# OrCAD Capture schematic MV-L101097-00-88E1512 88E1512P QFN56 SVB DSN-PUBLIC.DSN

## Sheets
1 Title Page: title: 88E1512 / 88E1512P 56-QFN Evaluation Board (Schematics); rev: -; note: MV-L101097-00
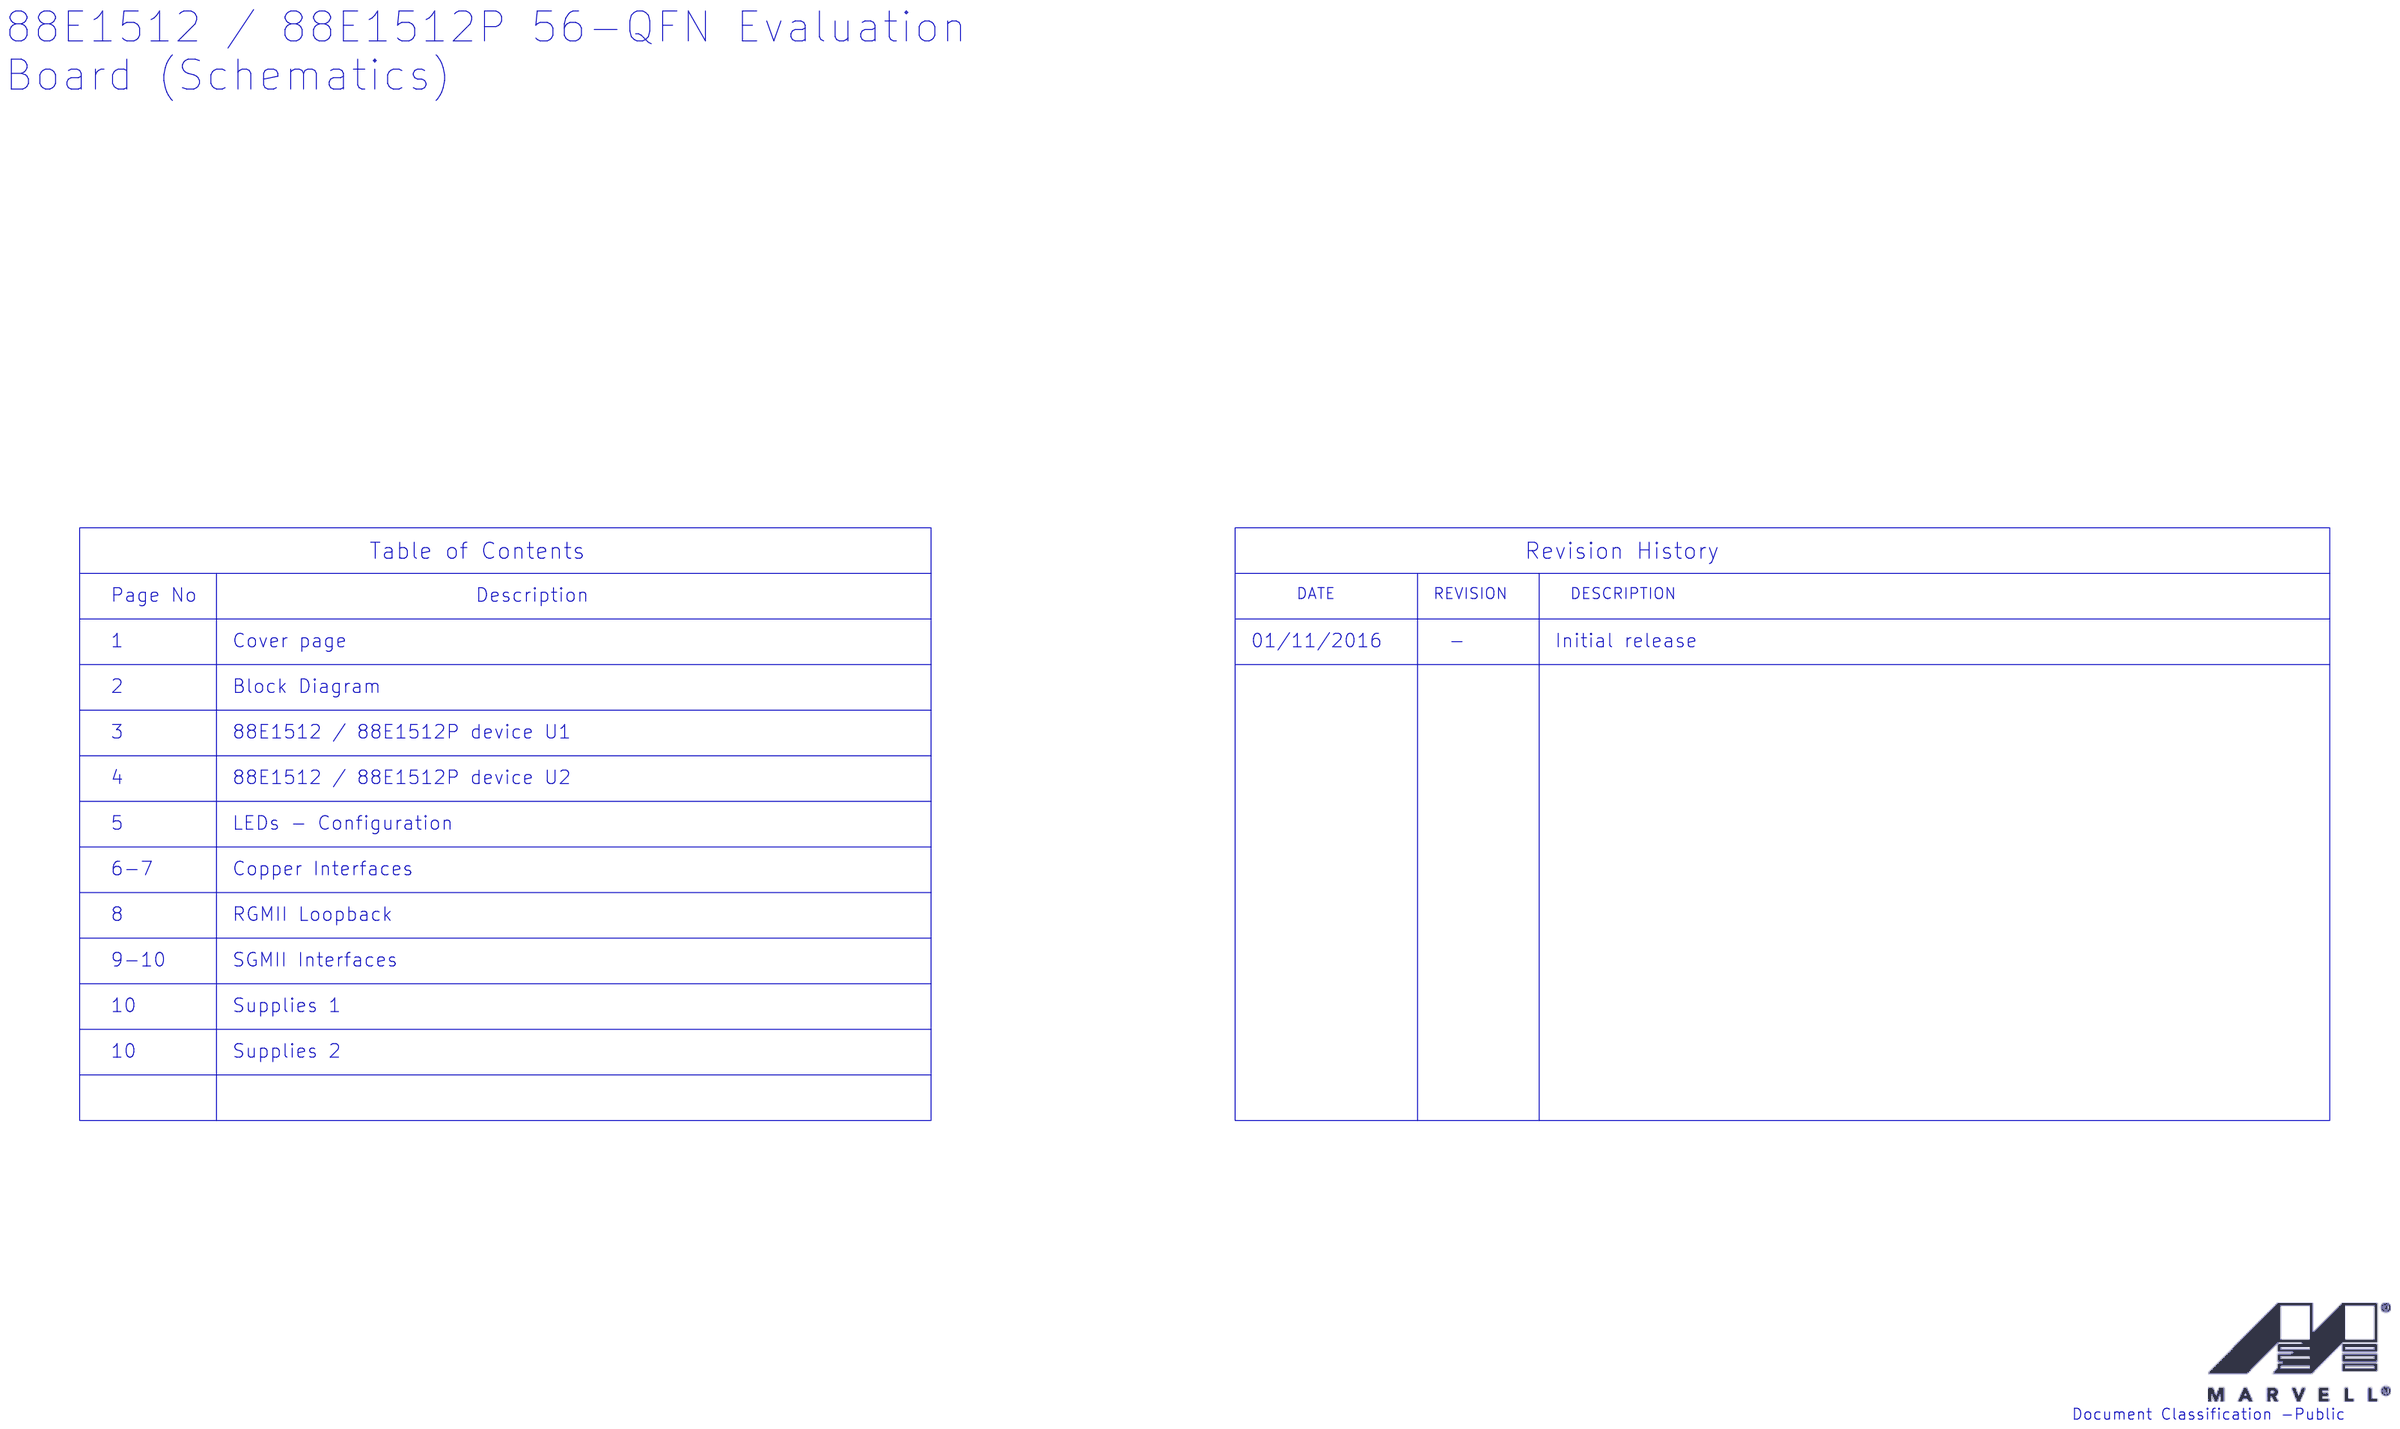
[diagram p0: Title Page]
2 Block Diagram
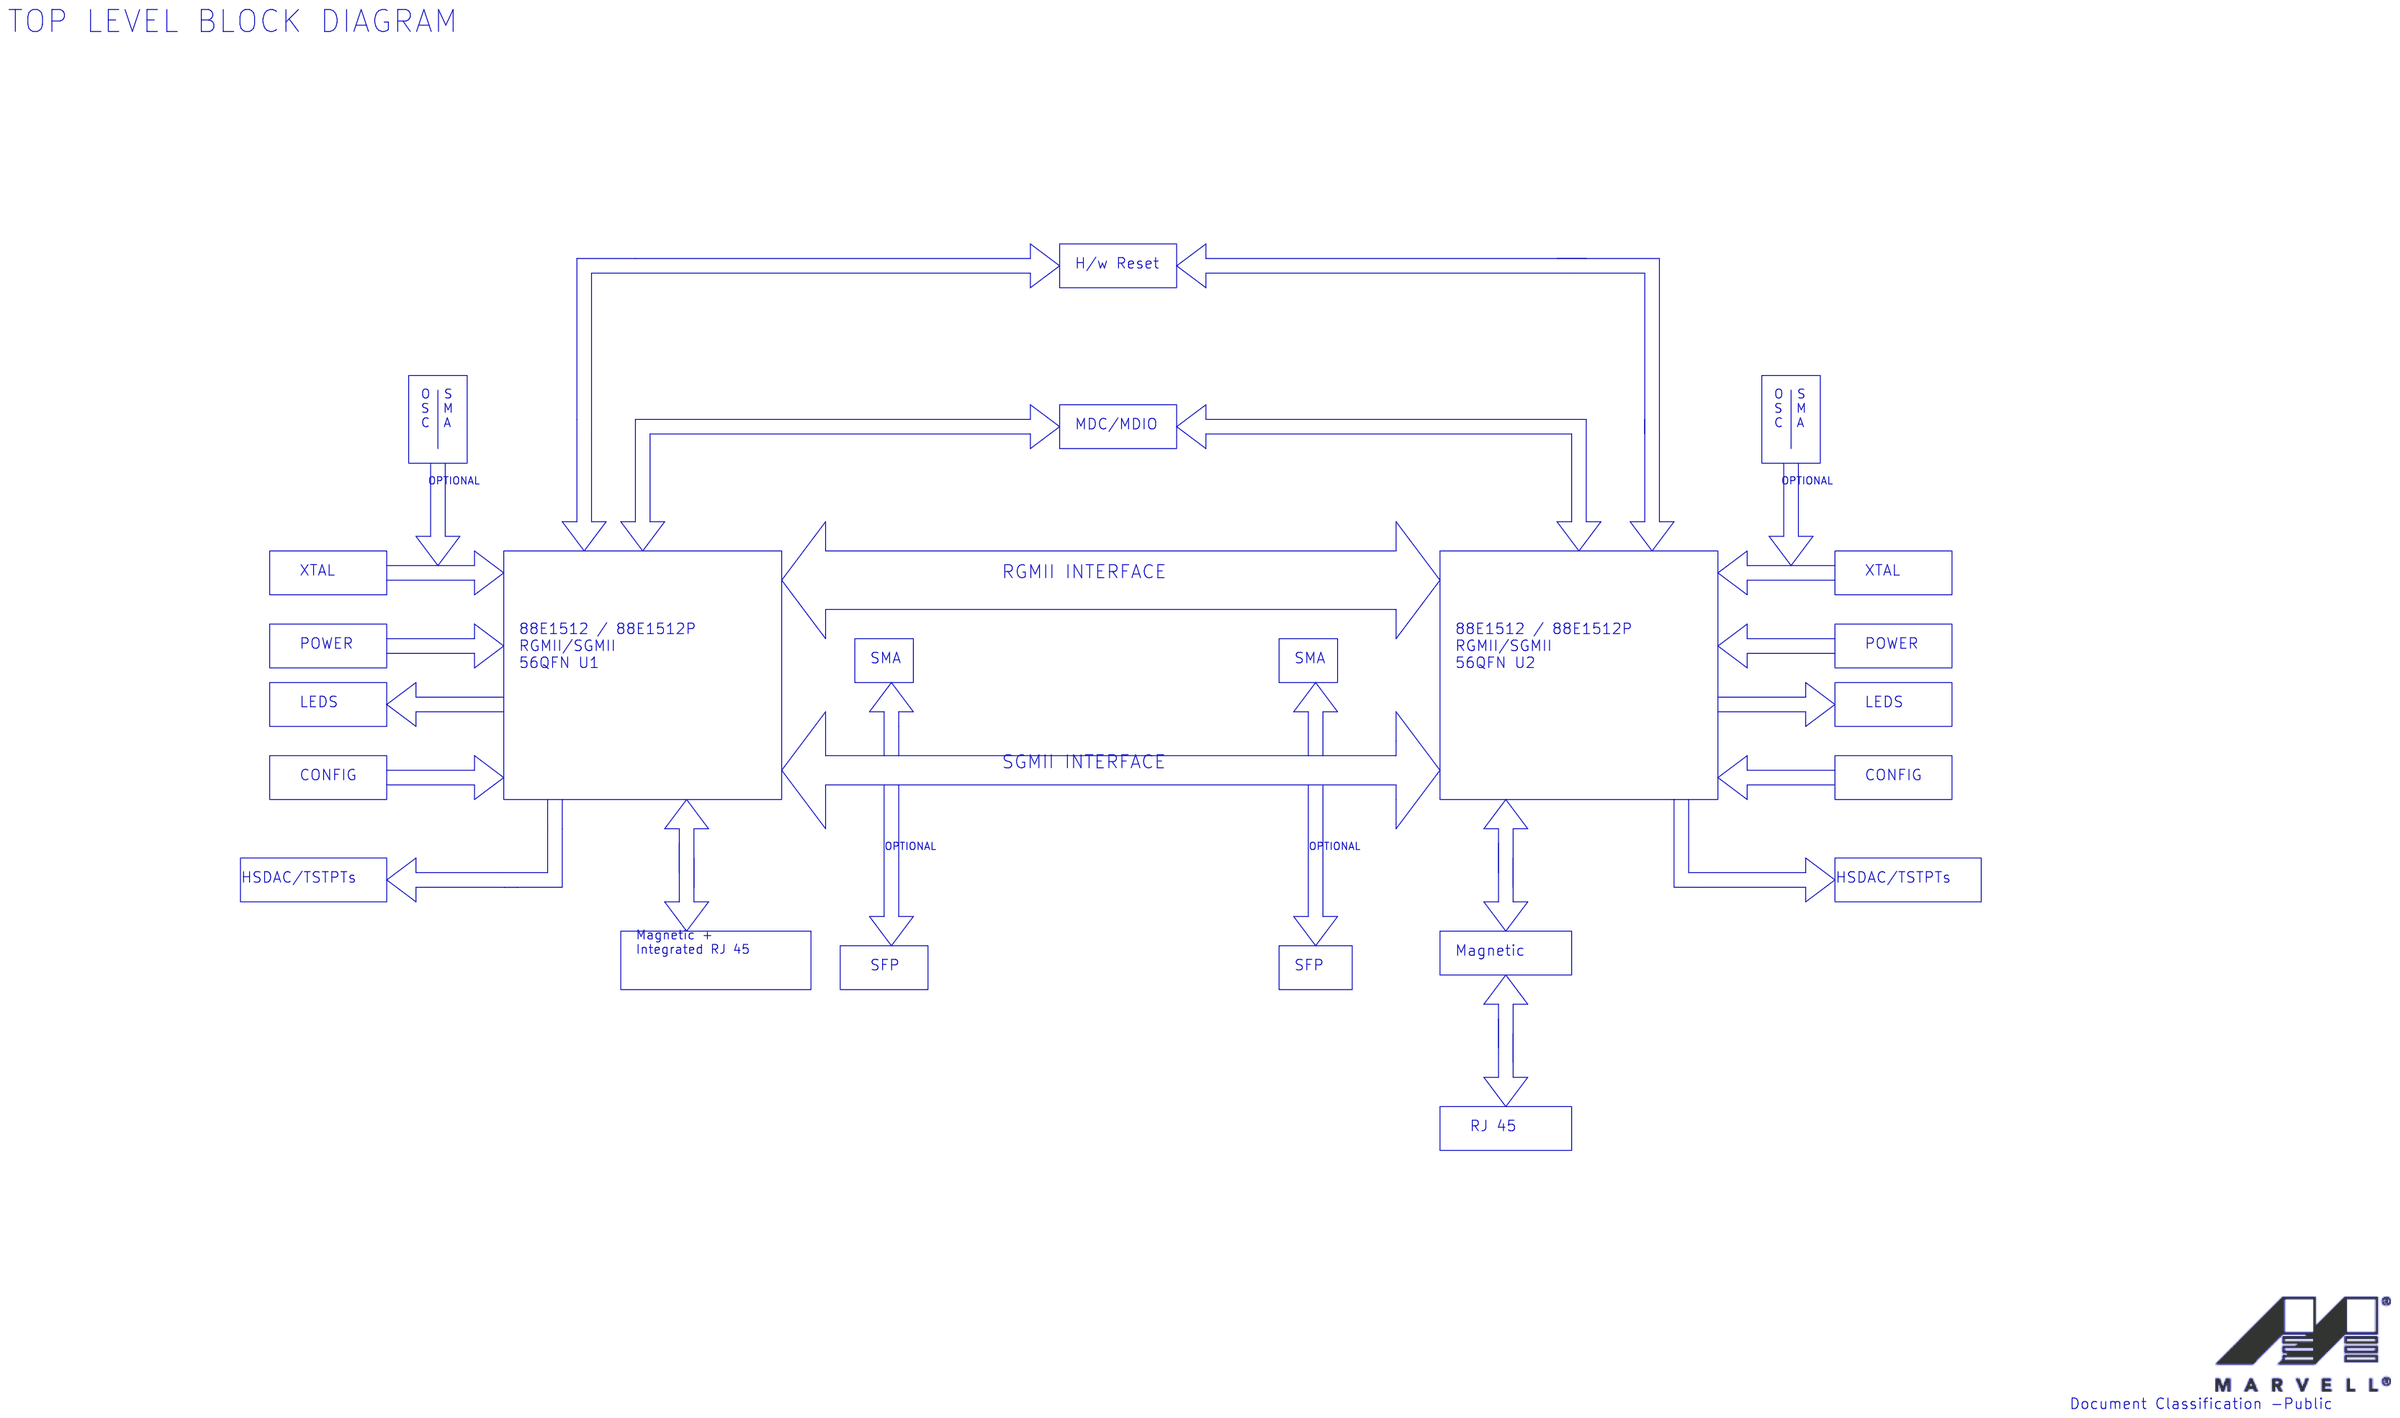
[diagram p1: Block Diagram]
3 88E1512 - U1: size Custom
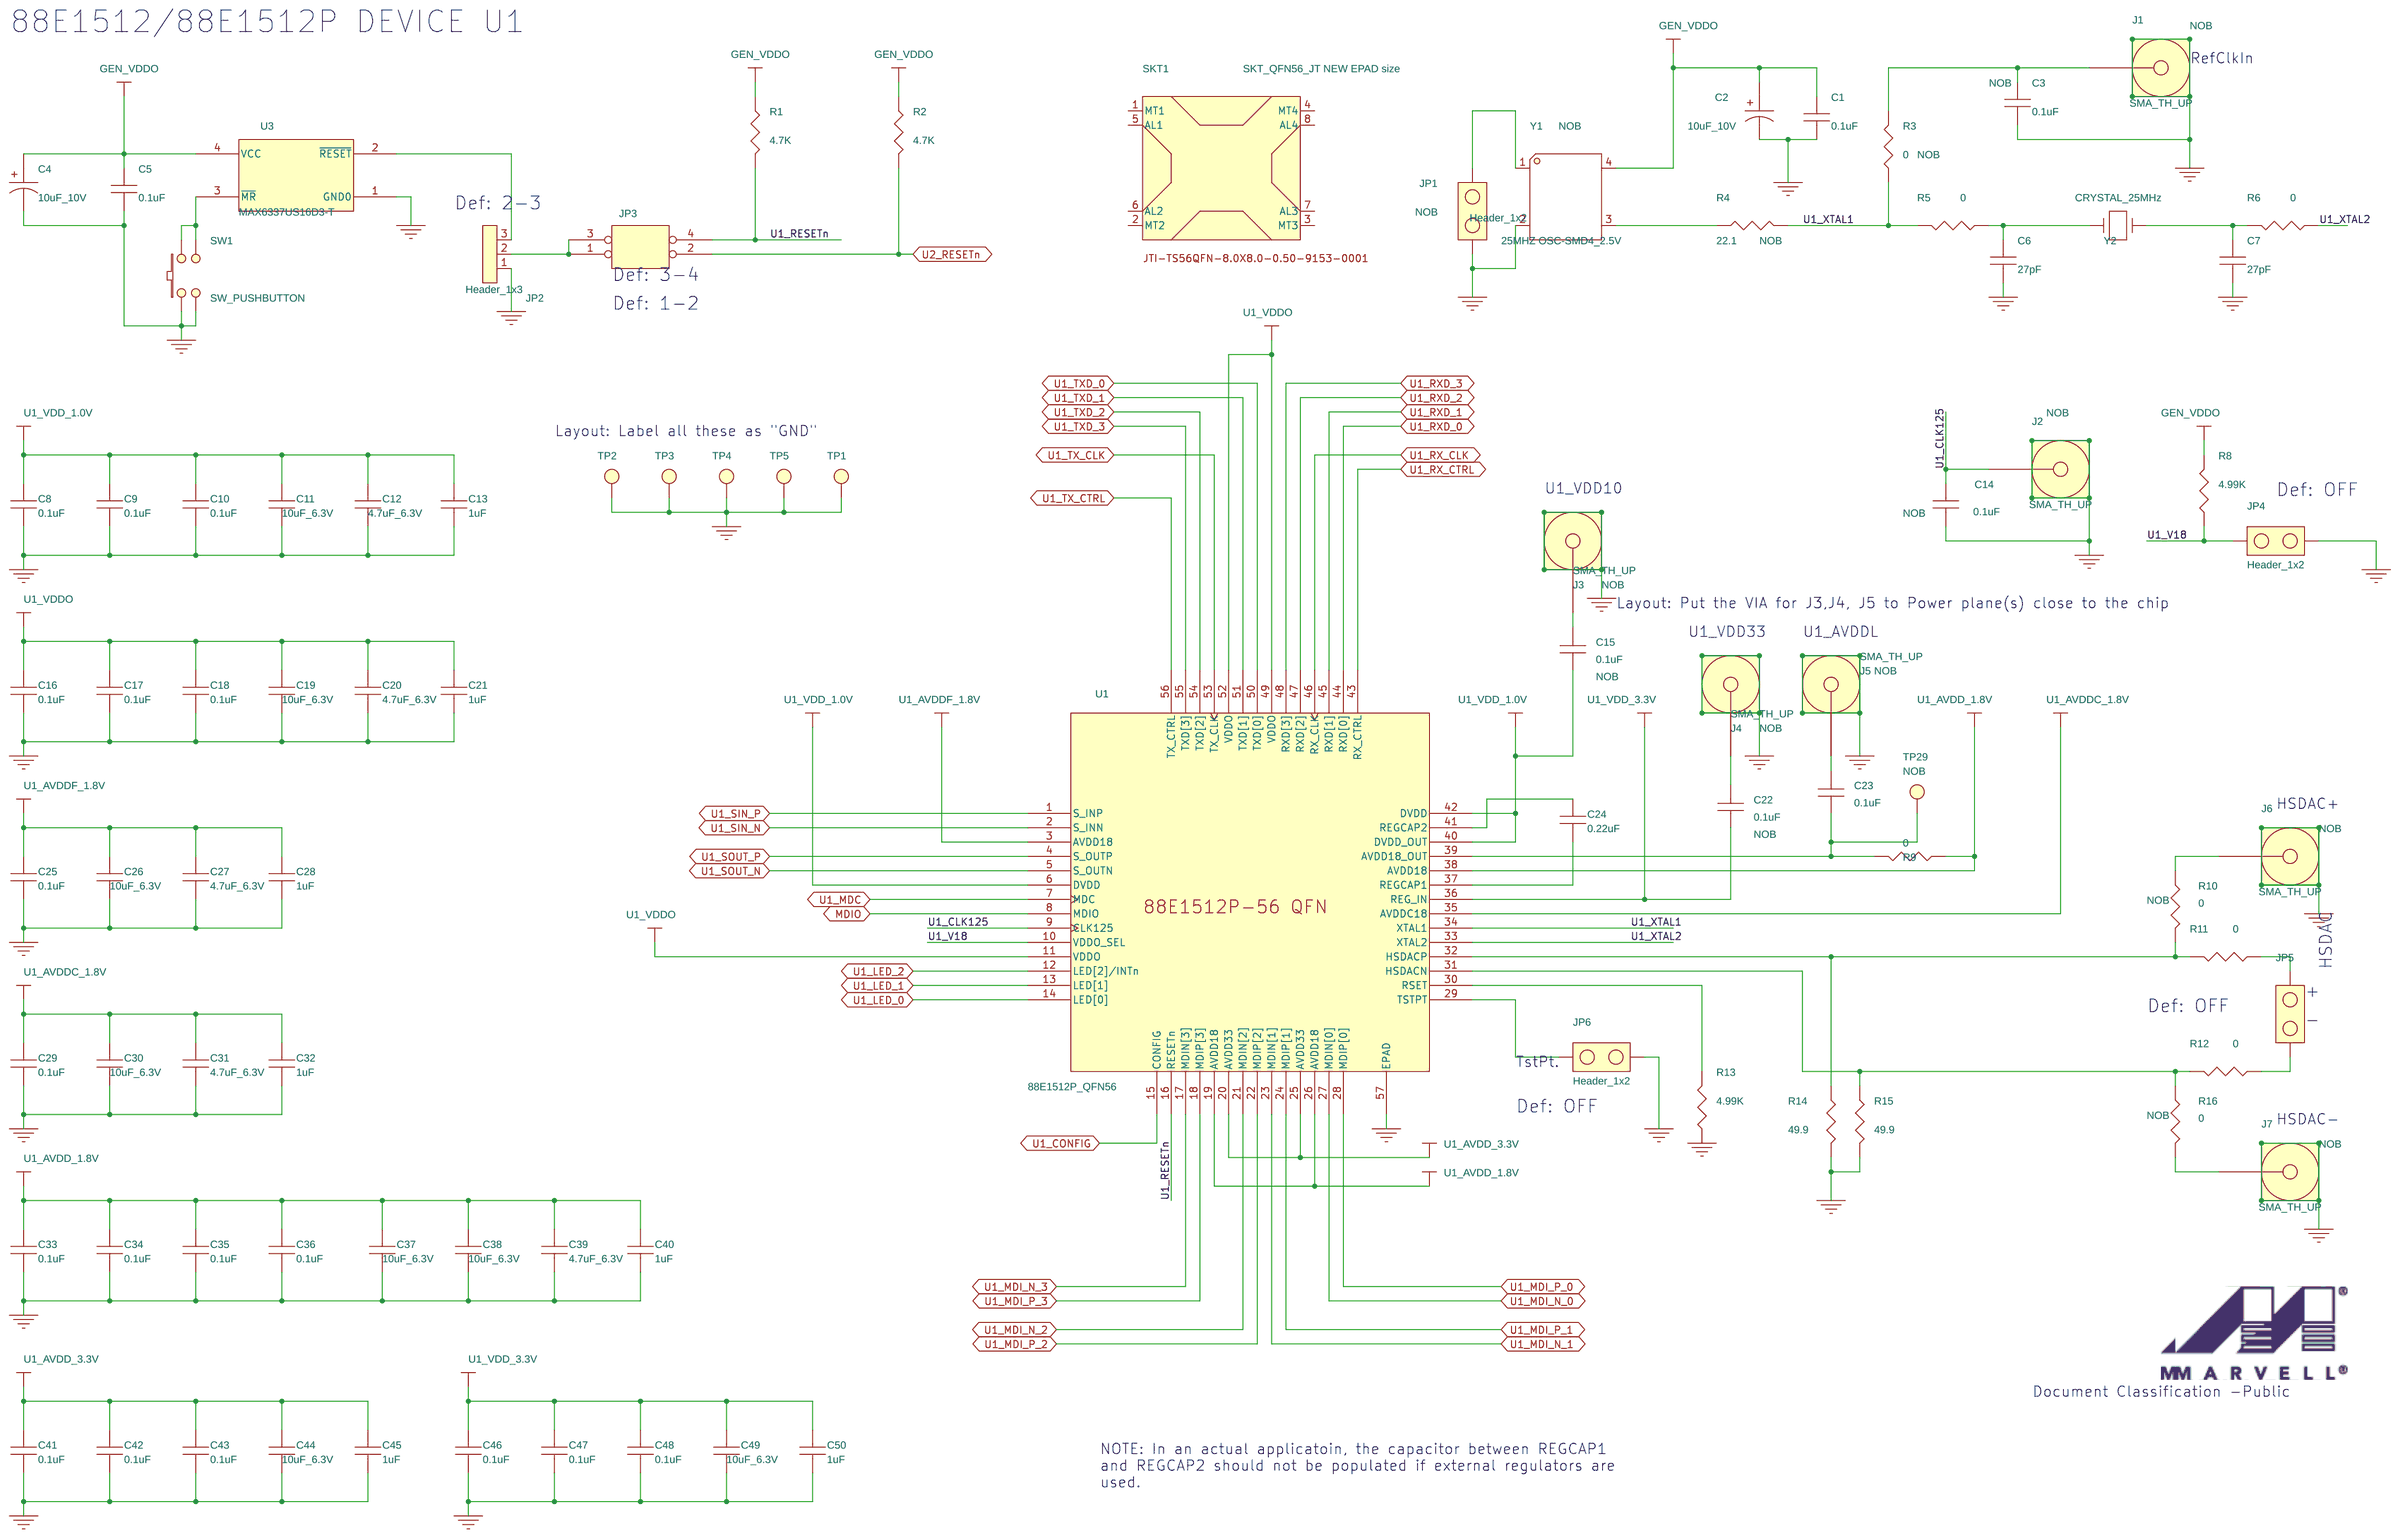
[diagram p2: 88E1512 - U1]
4 88E1512 - U2: size Custom
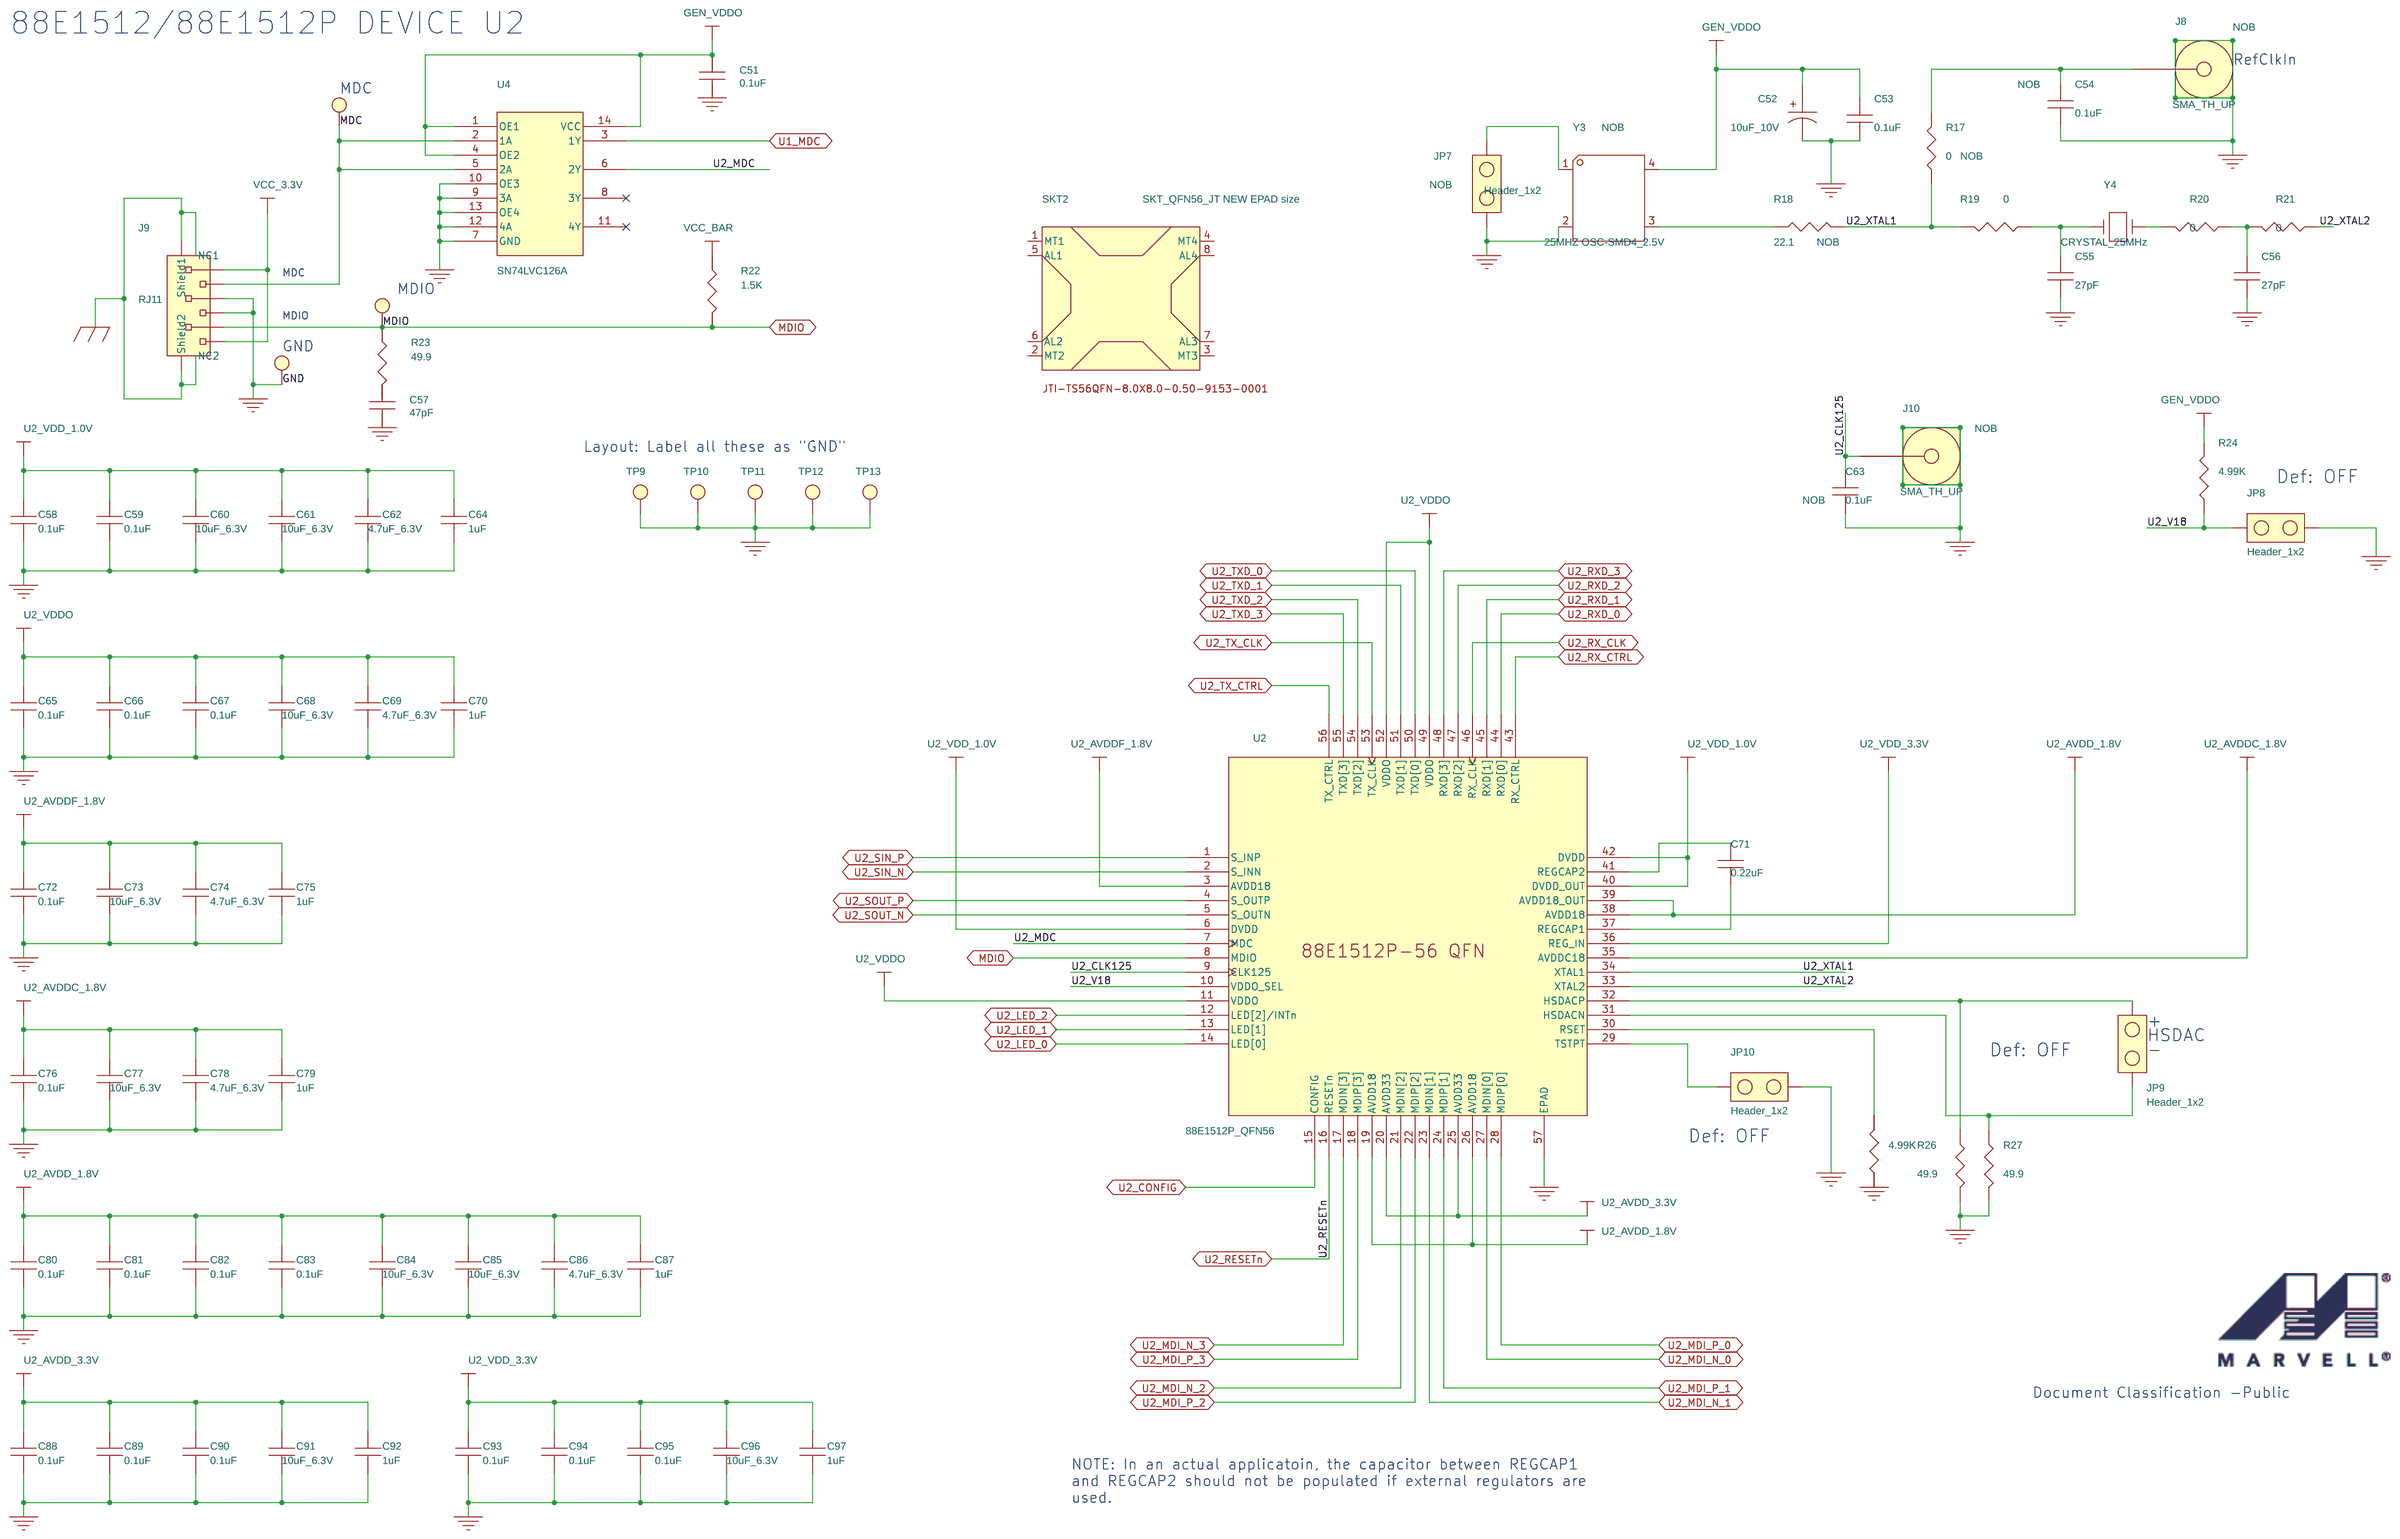
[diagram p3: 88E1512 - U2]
5 LEDs - Configuration: size Custom
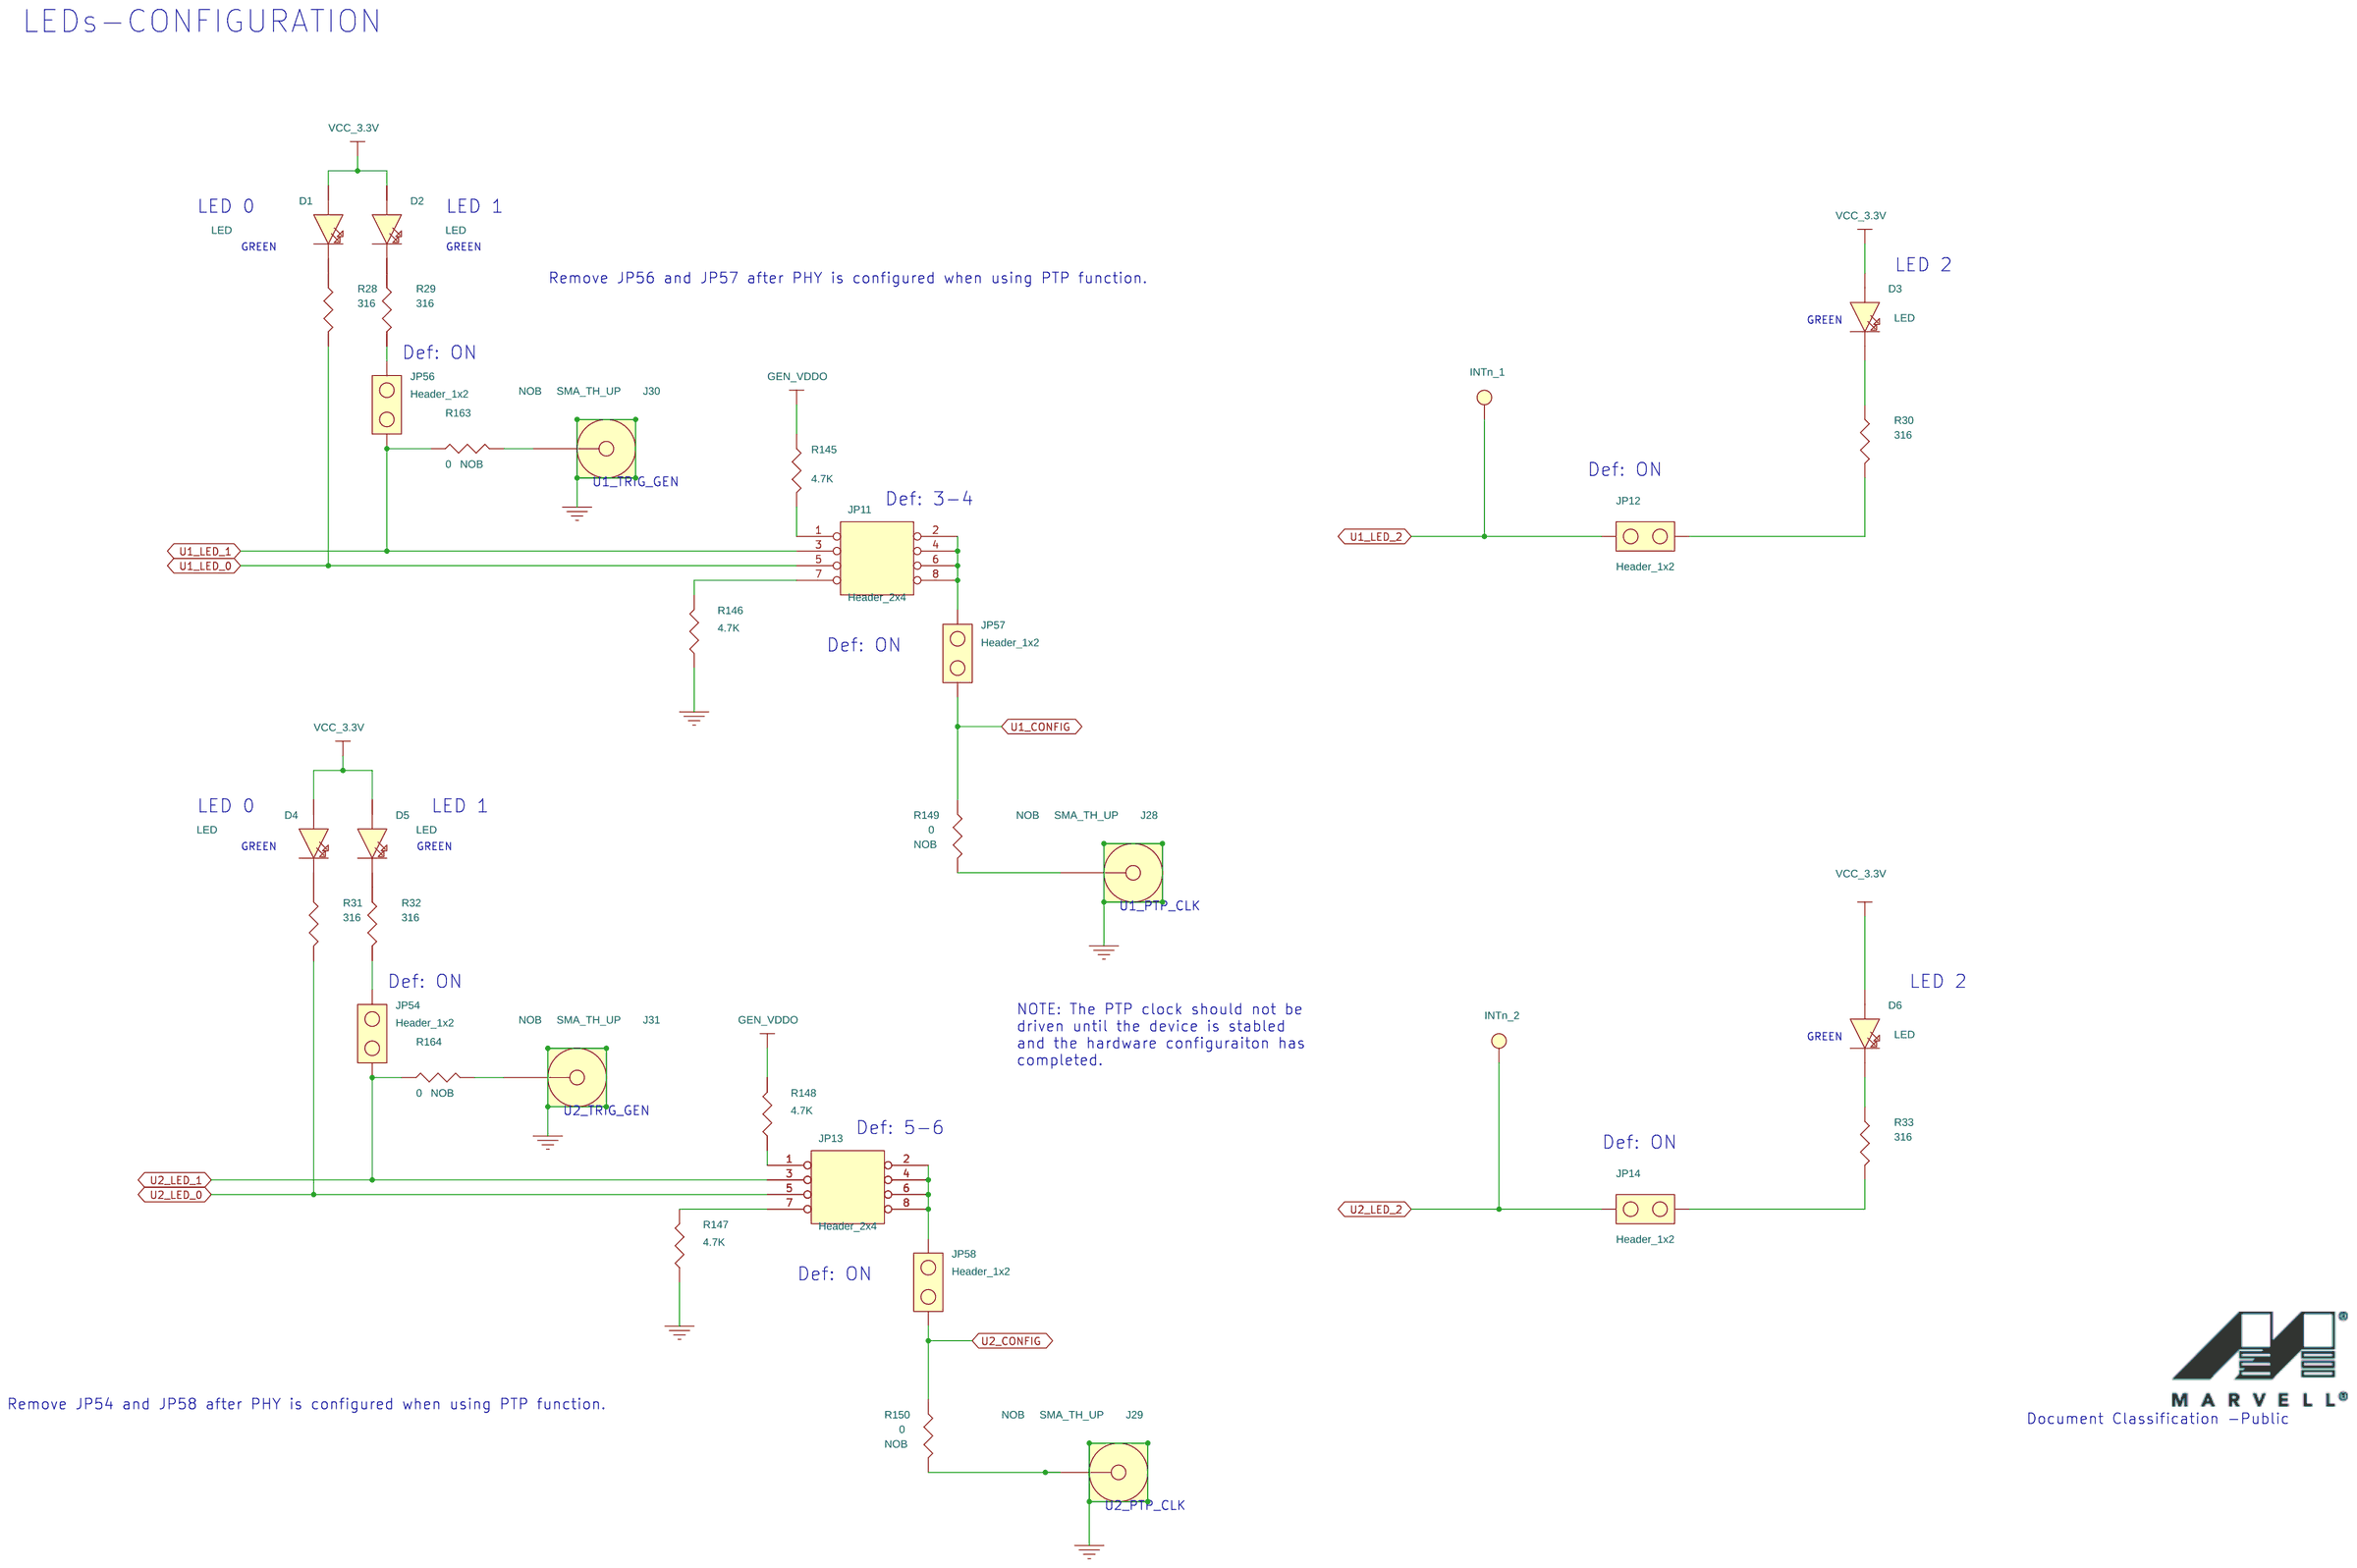
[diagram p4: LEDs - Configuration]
6 U1 Copper Media: size Custom
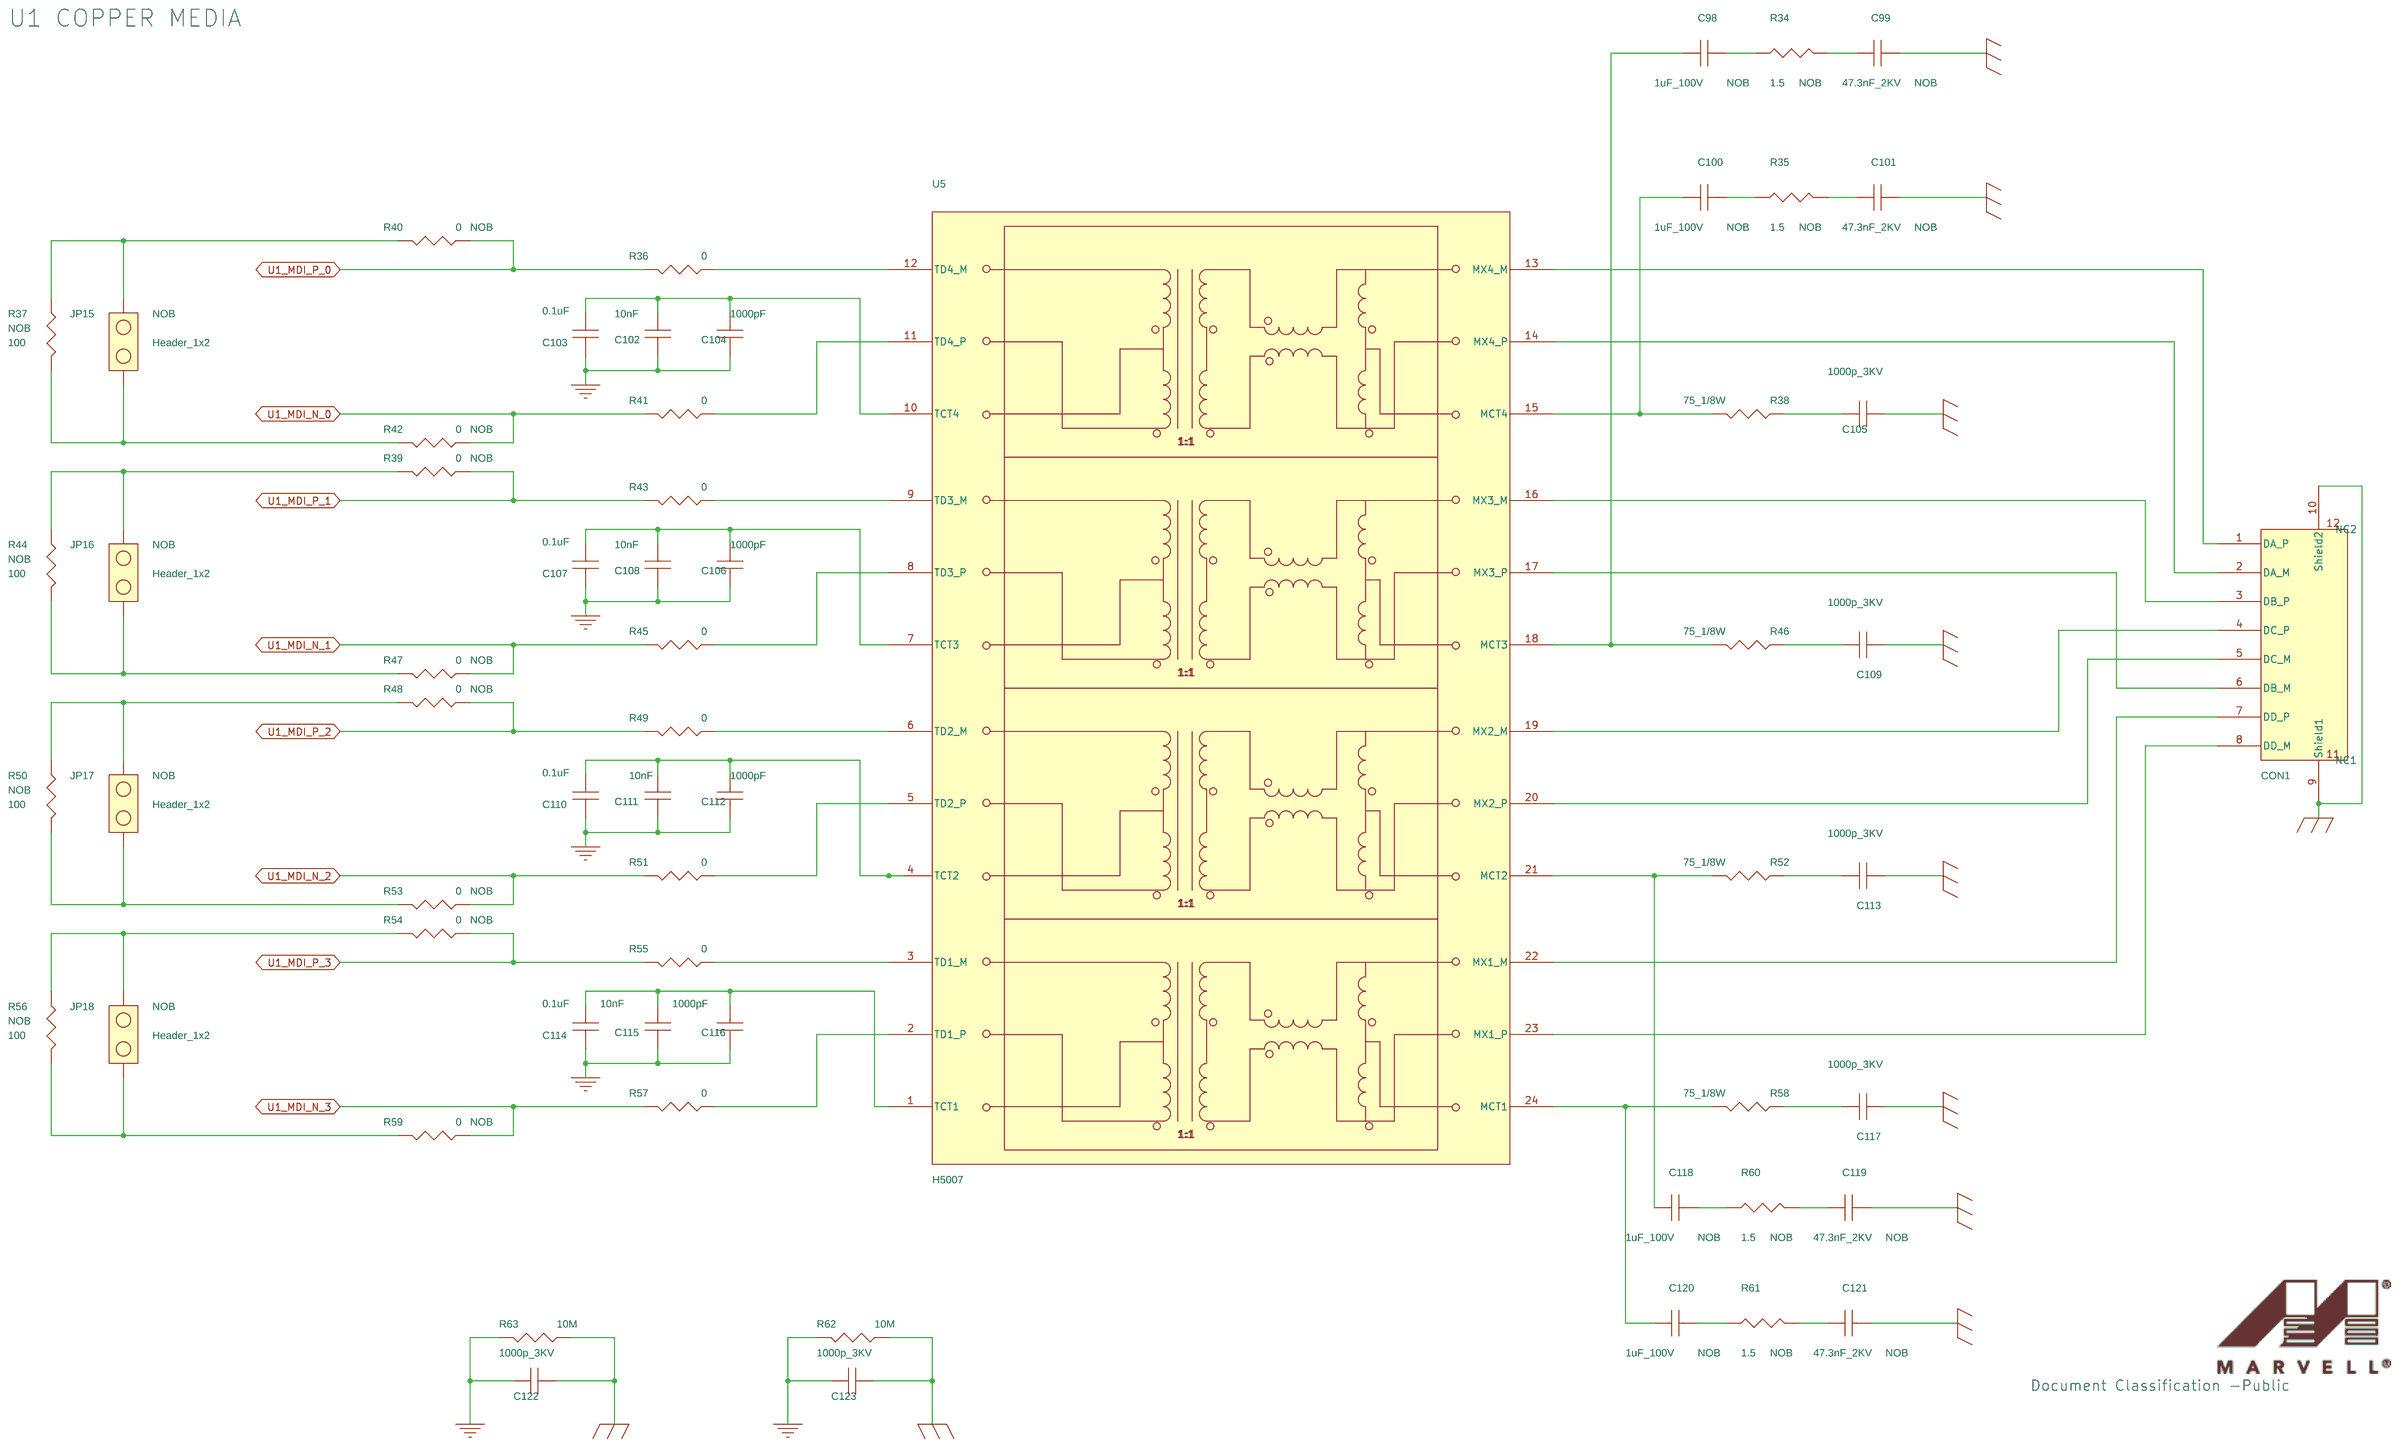
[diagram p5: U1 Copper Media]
7 U2 Copper Media: size Custom
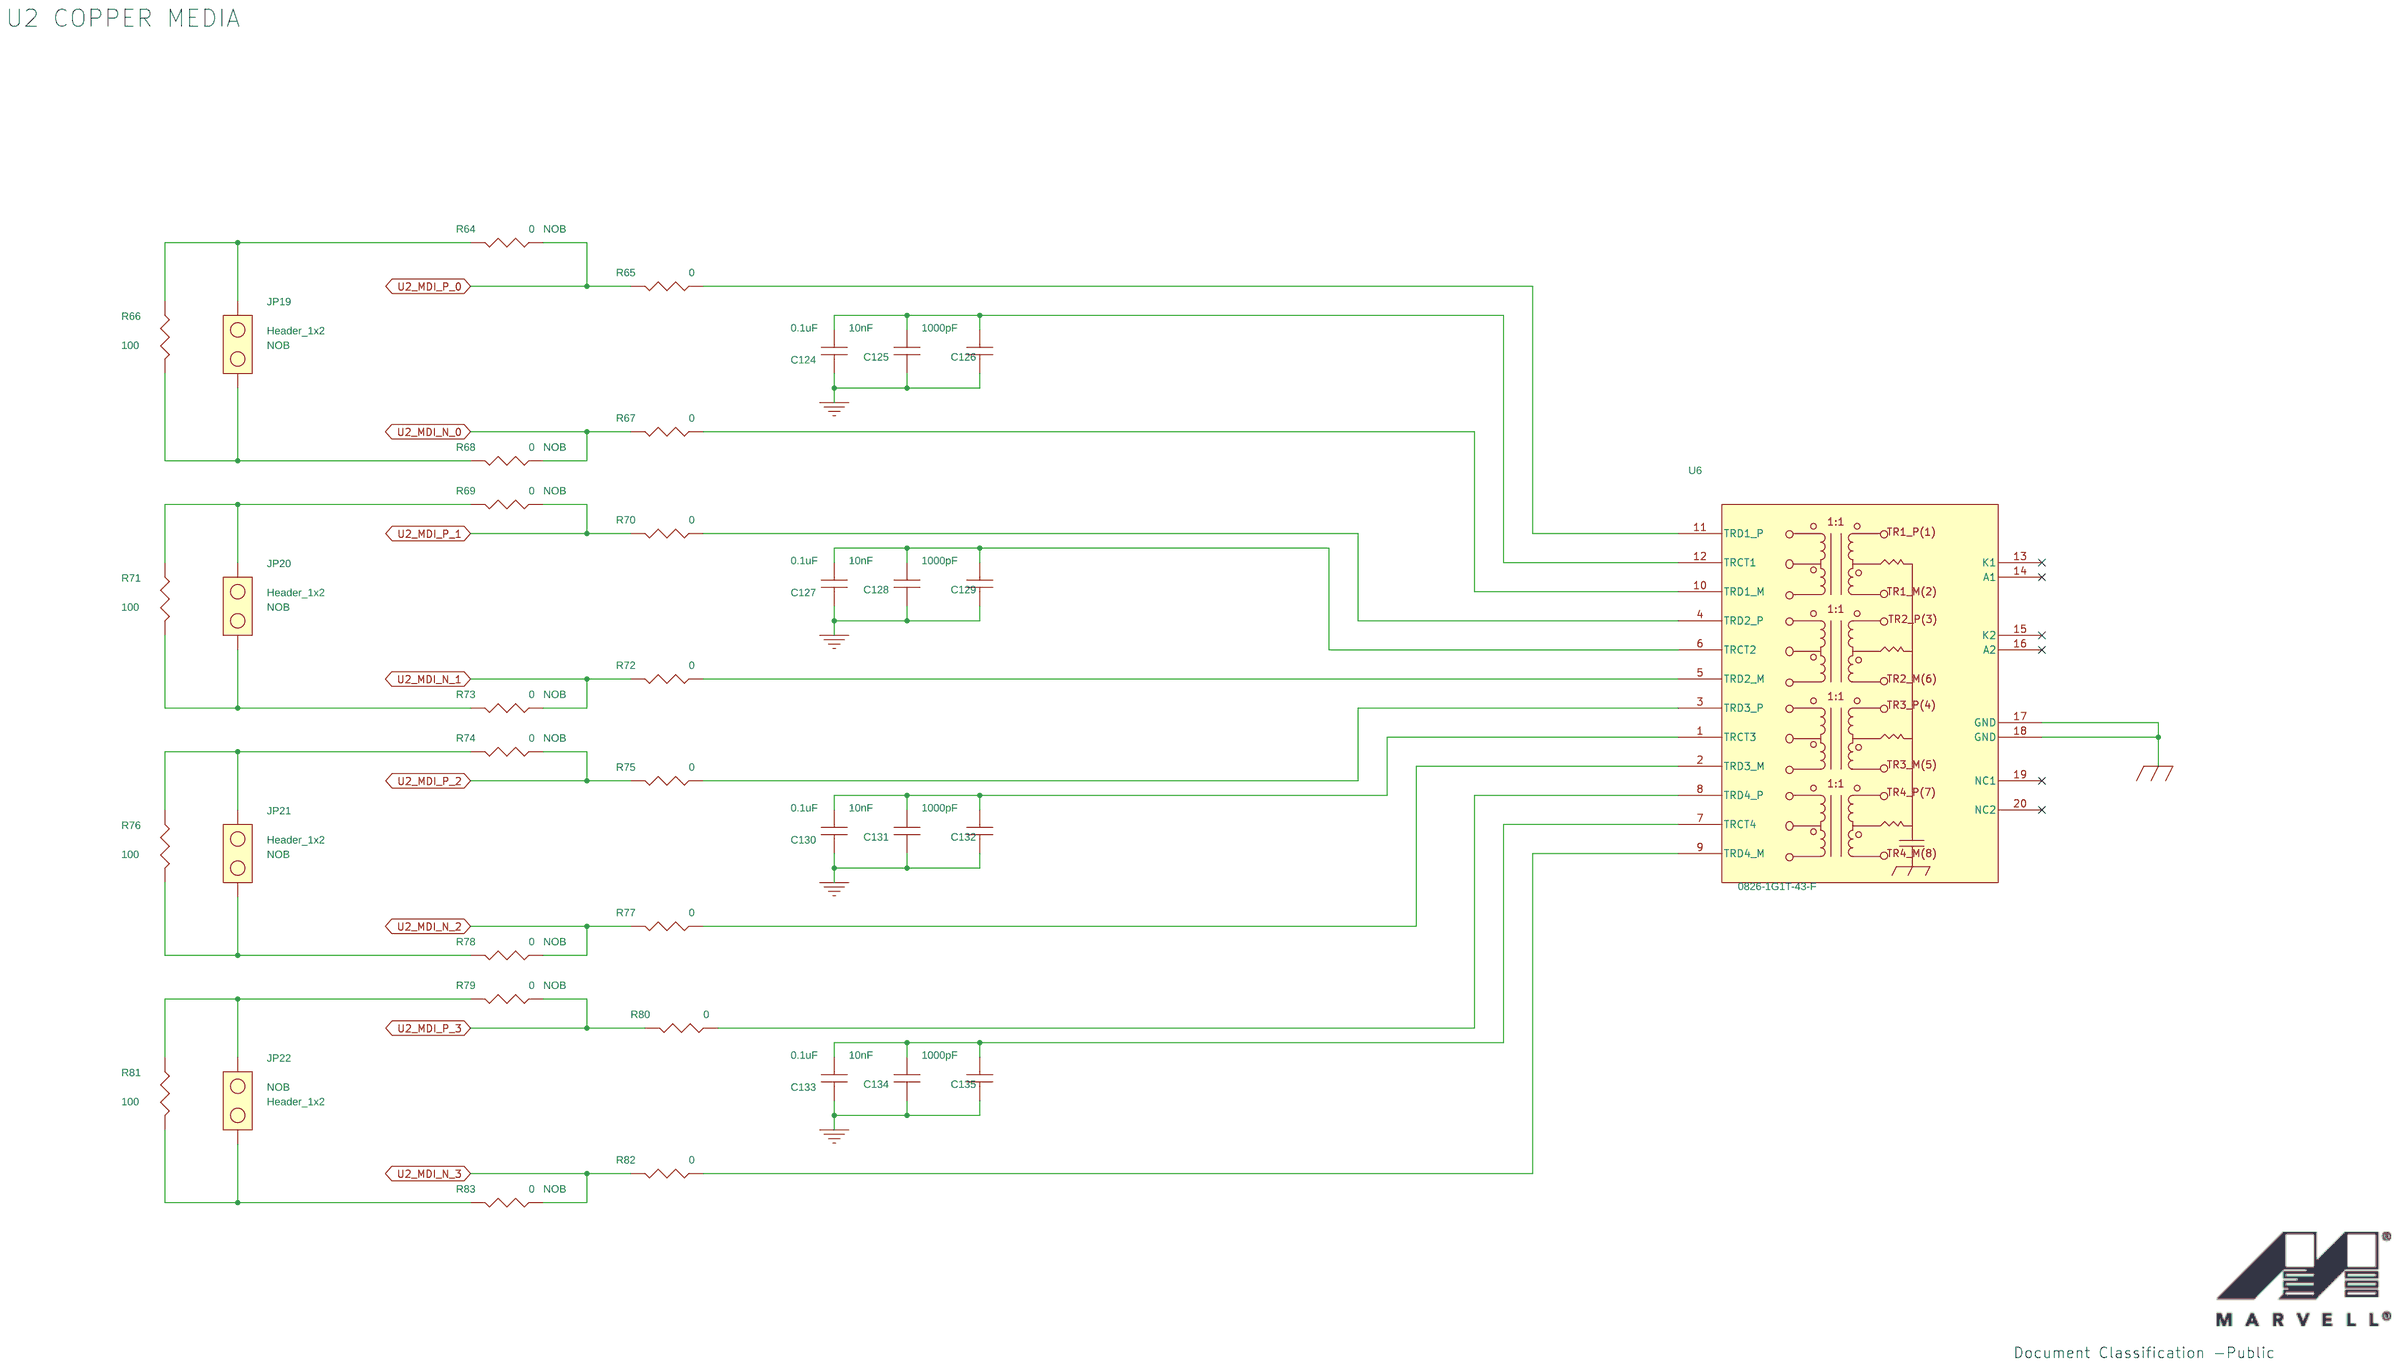
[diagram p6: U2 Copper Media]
8 RGMII LB OPTION: size Custom
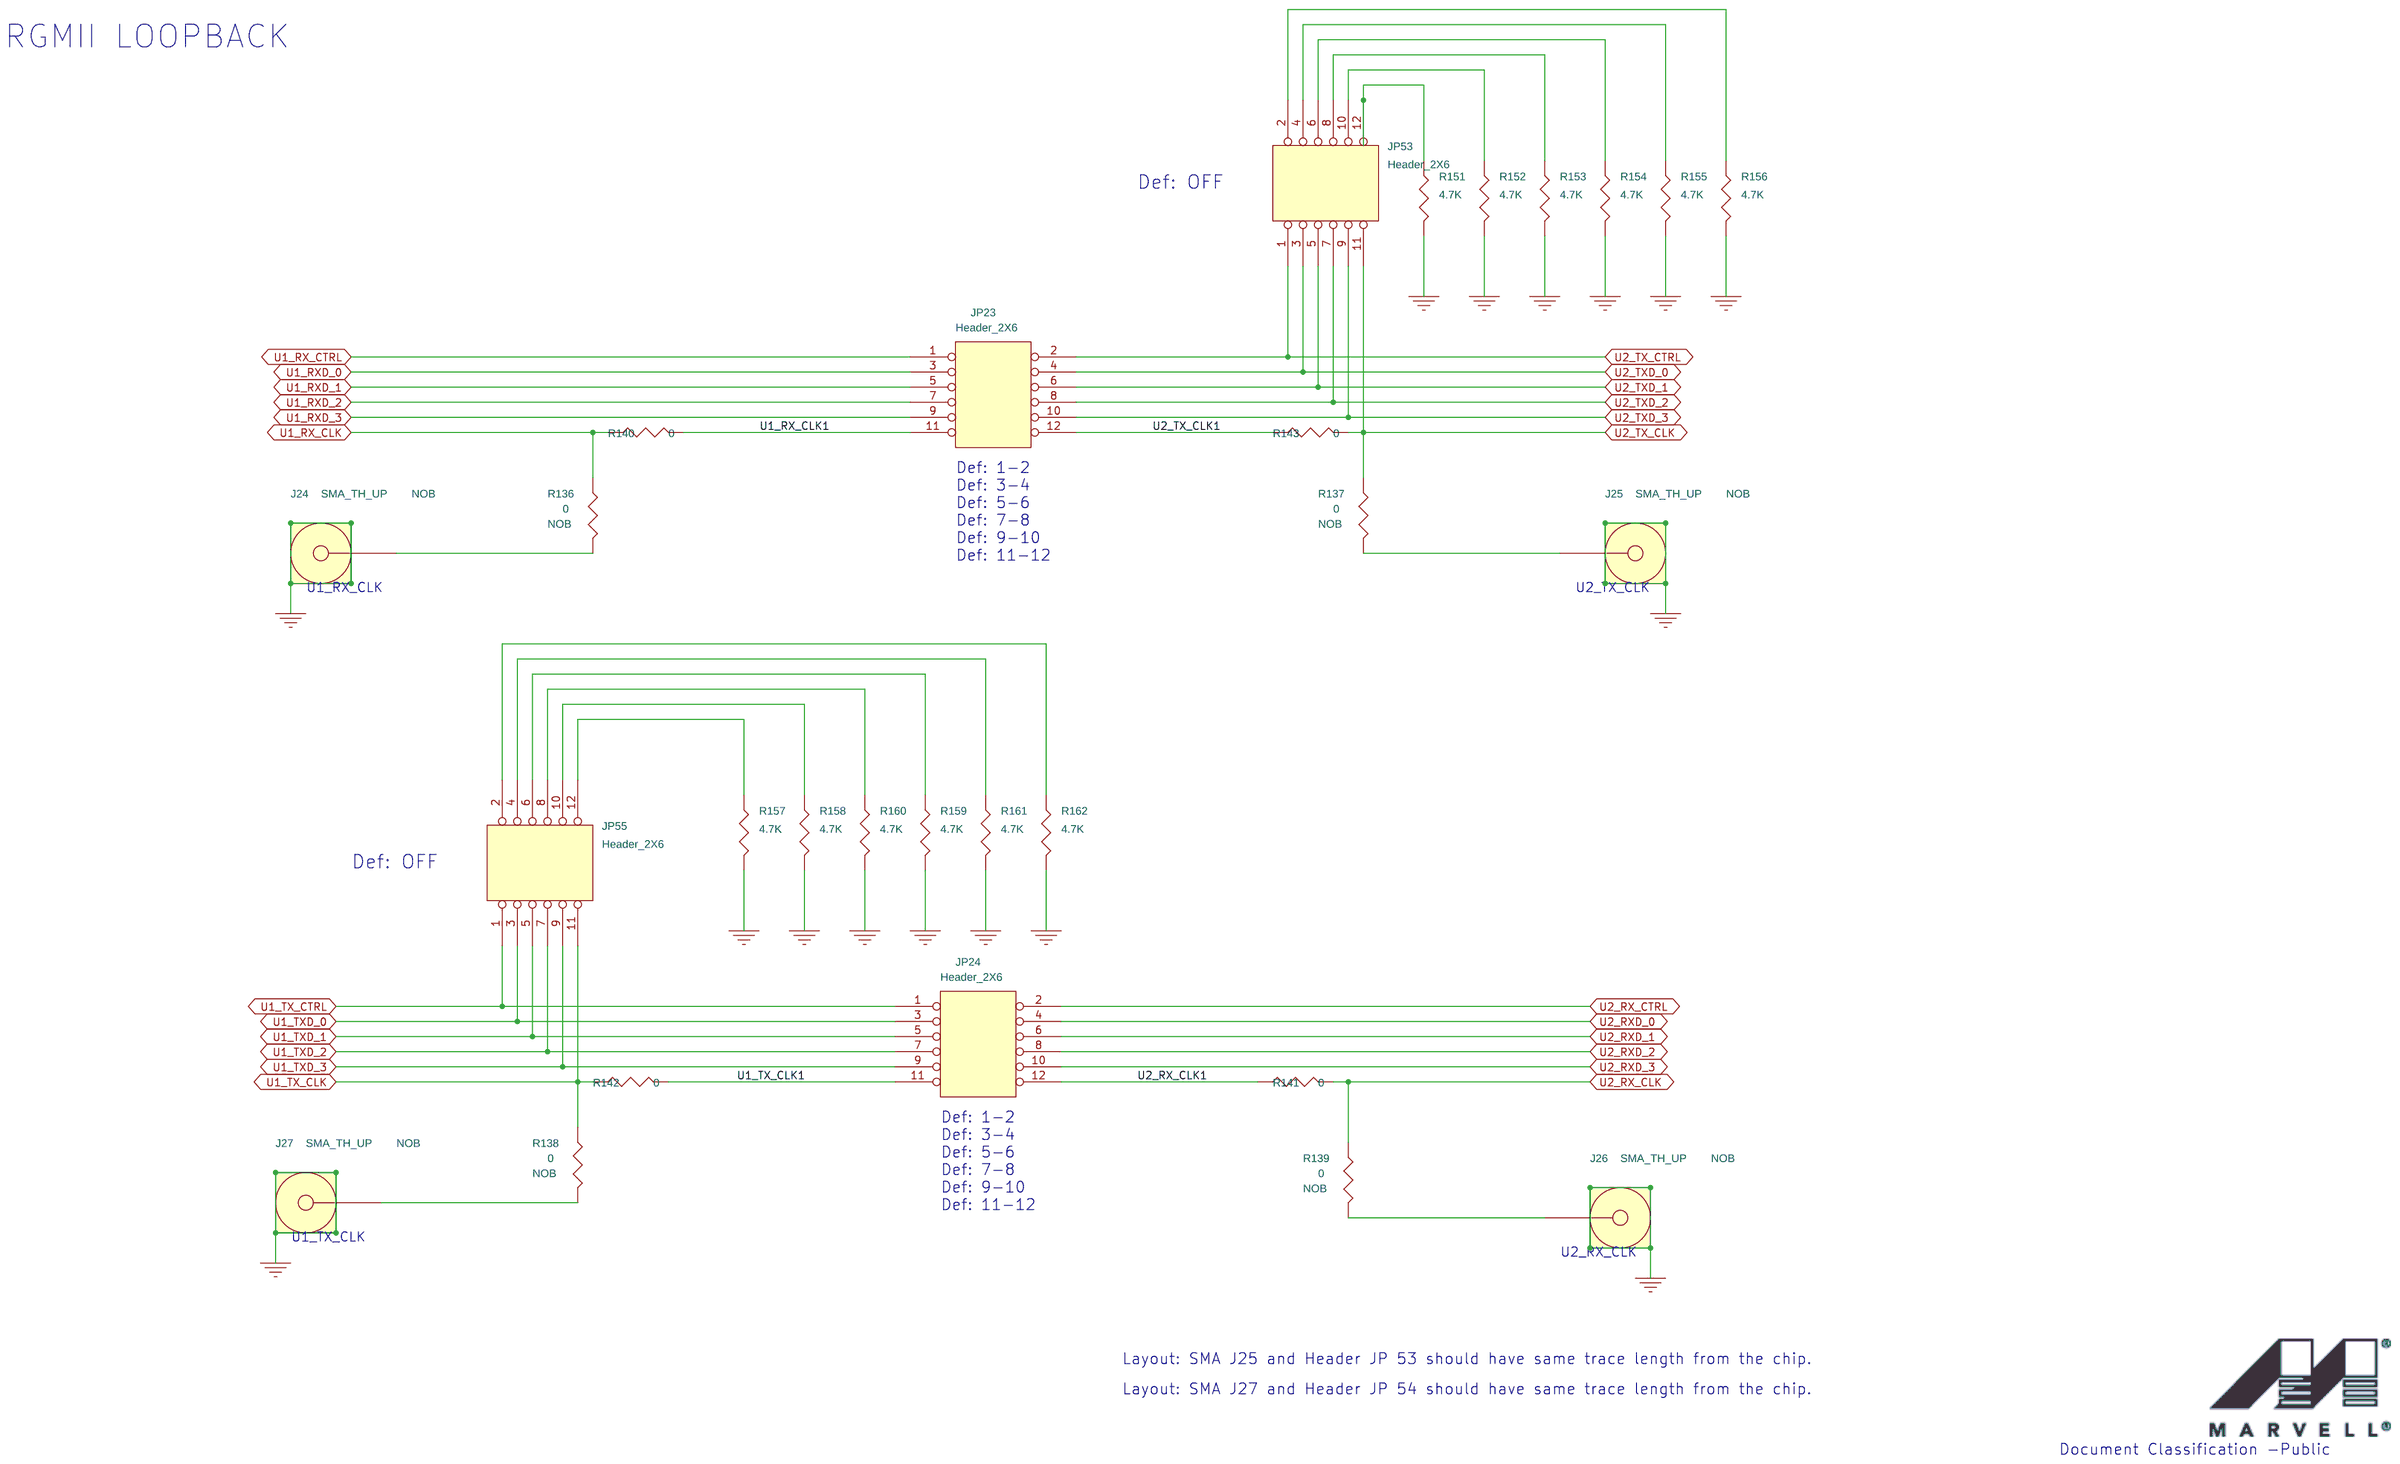
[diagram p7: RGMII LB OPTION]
9 U1 SGMII: size Custom
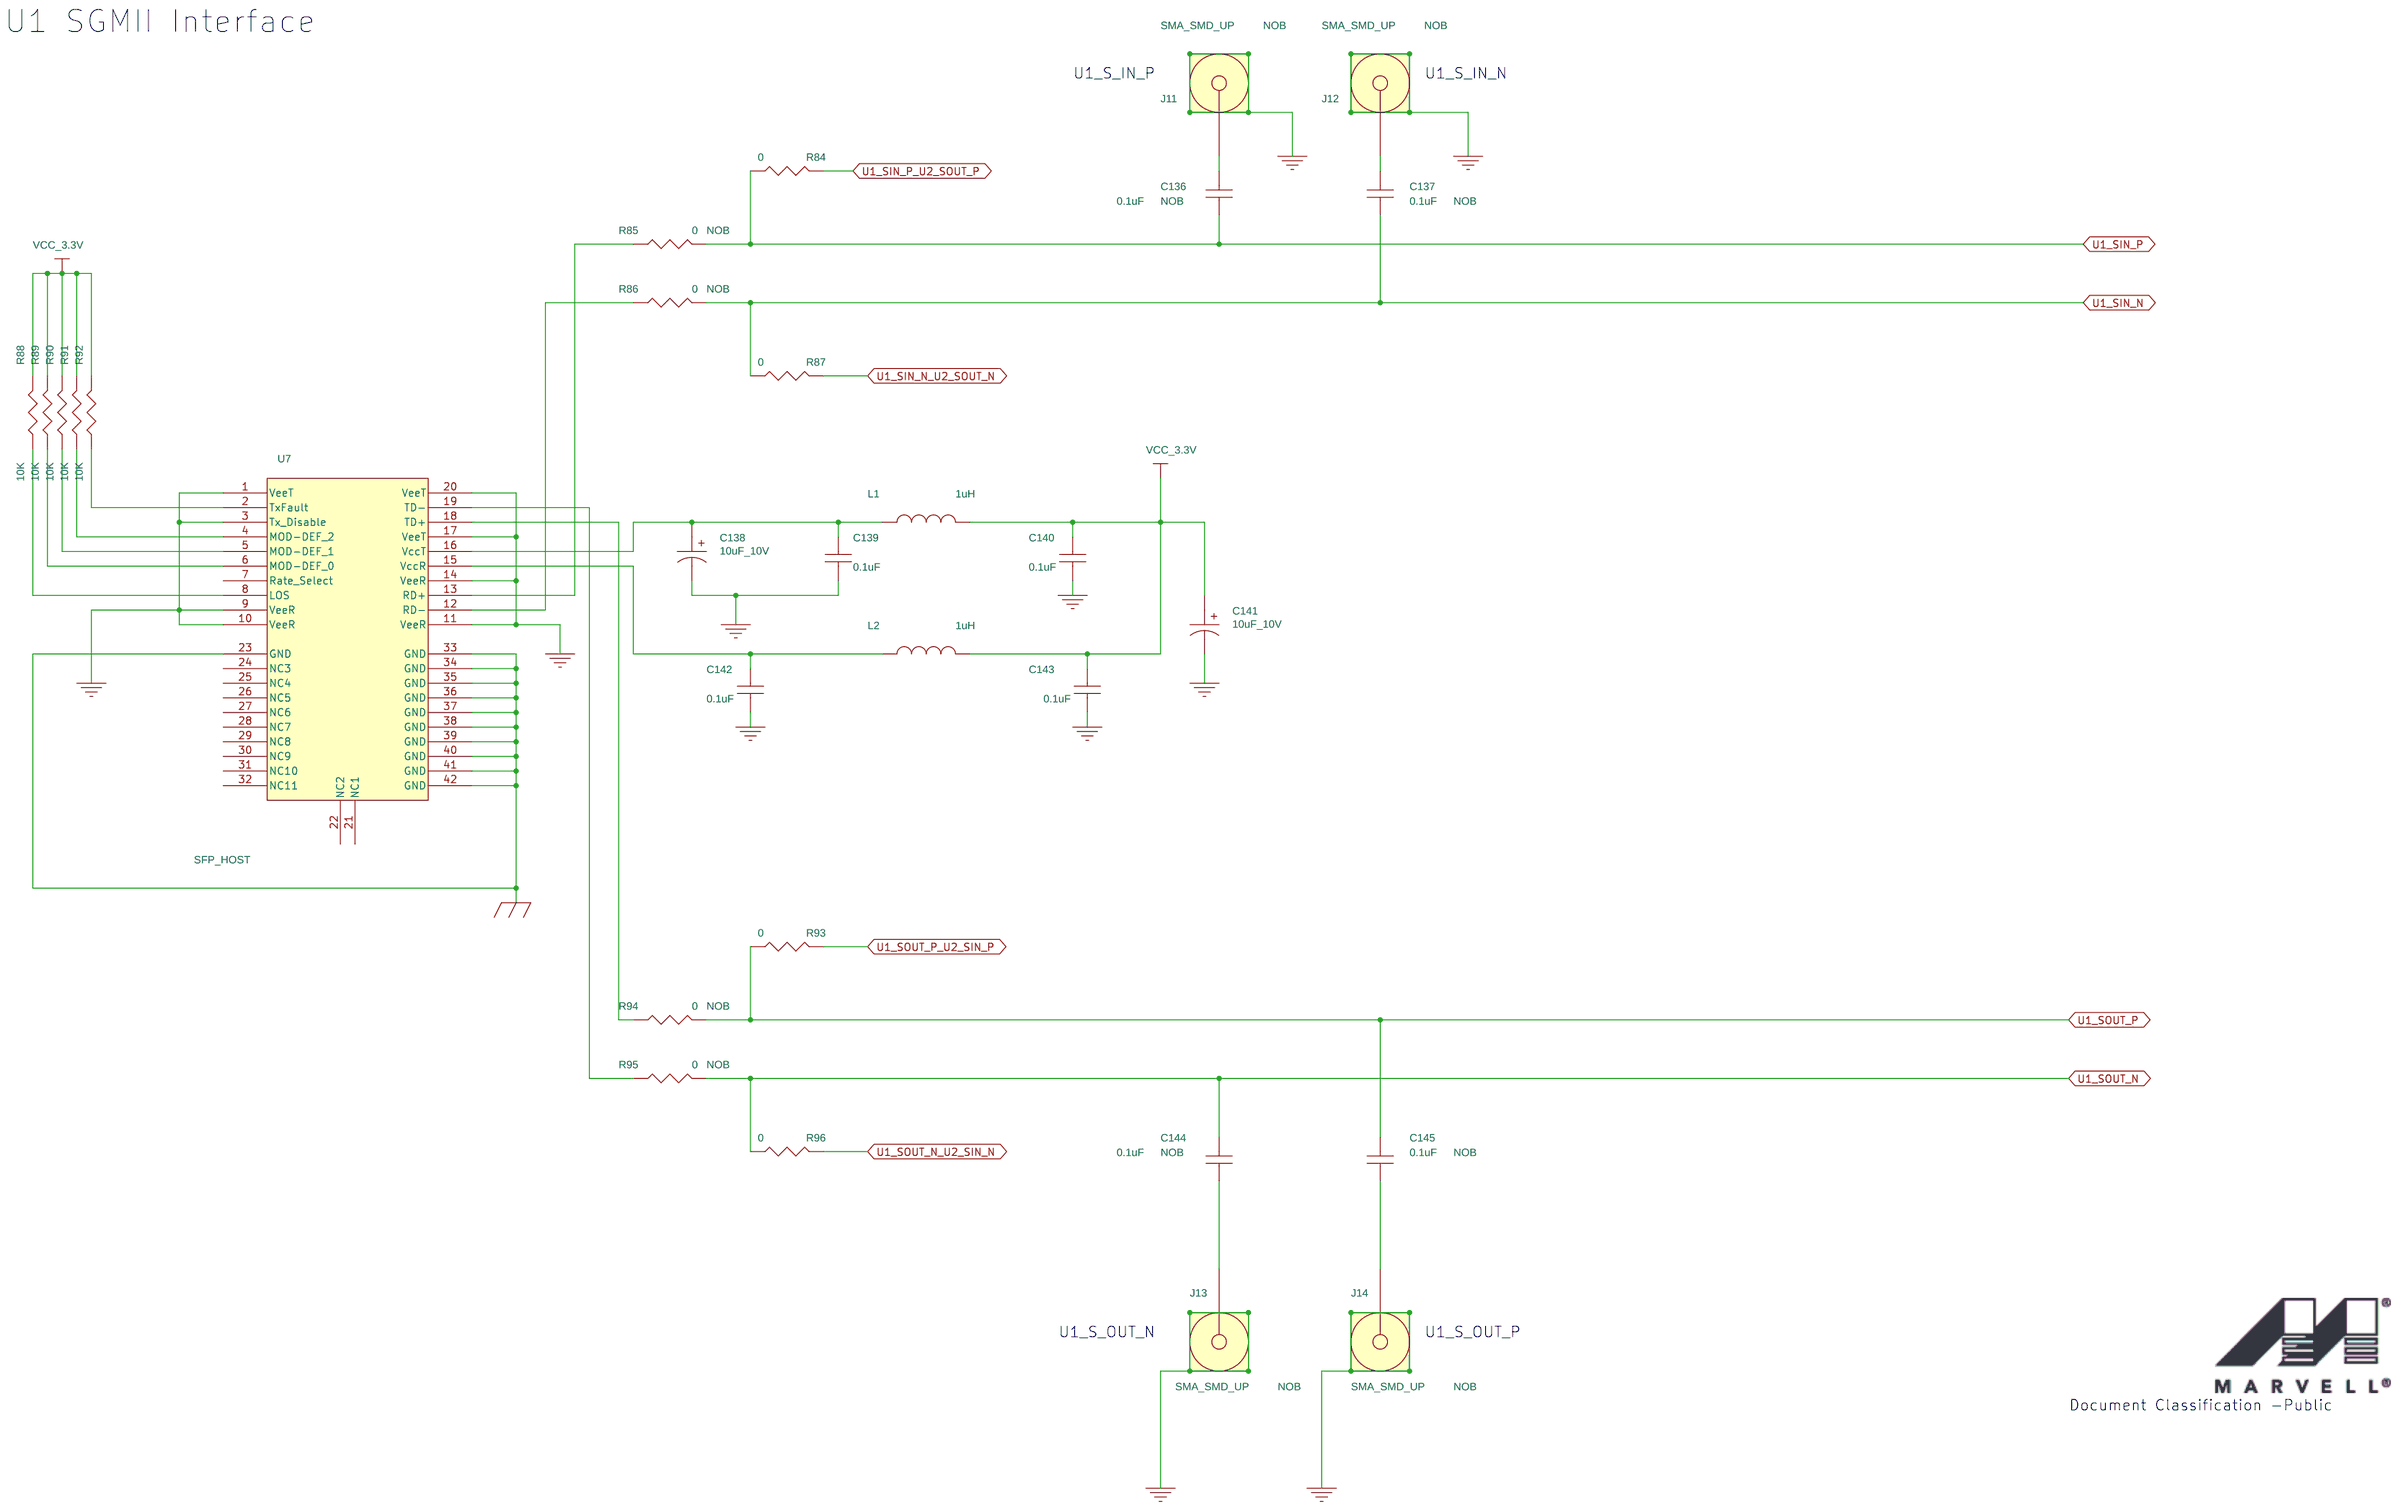
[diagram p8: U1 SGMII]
10 U2 SGMII: size Custom
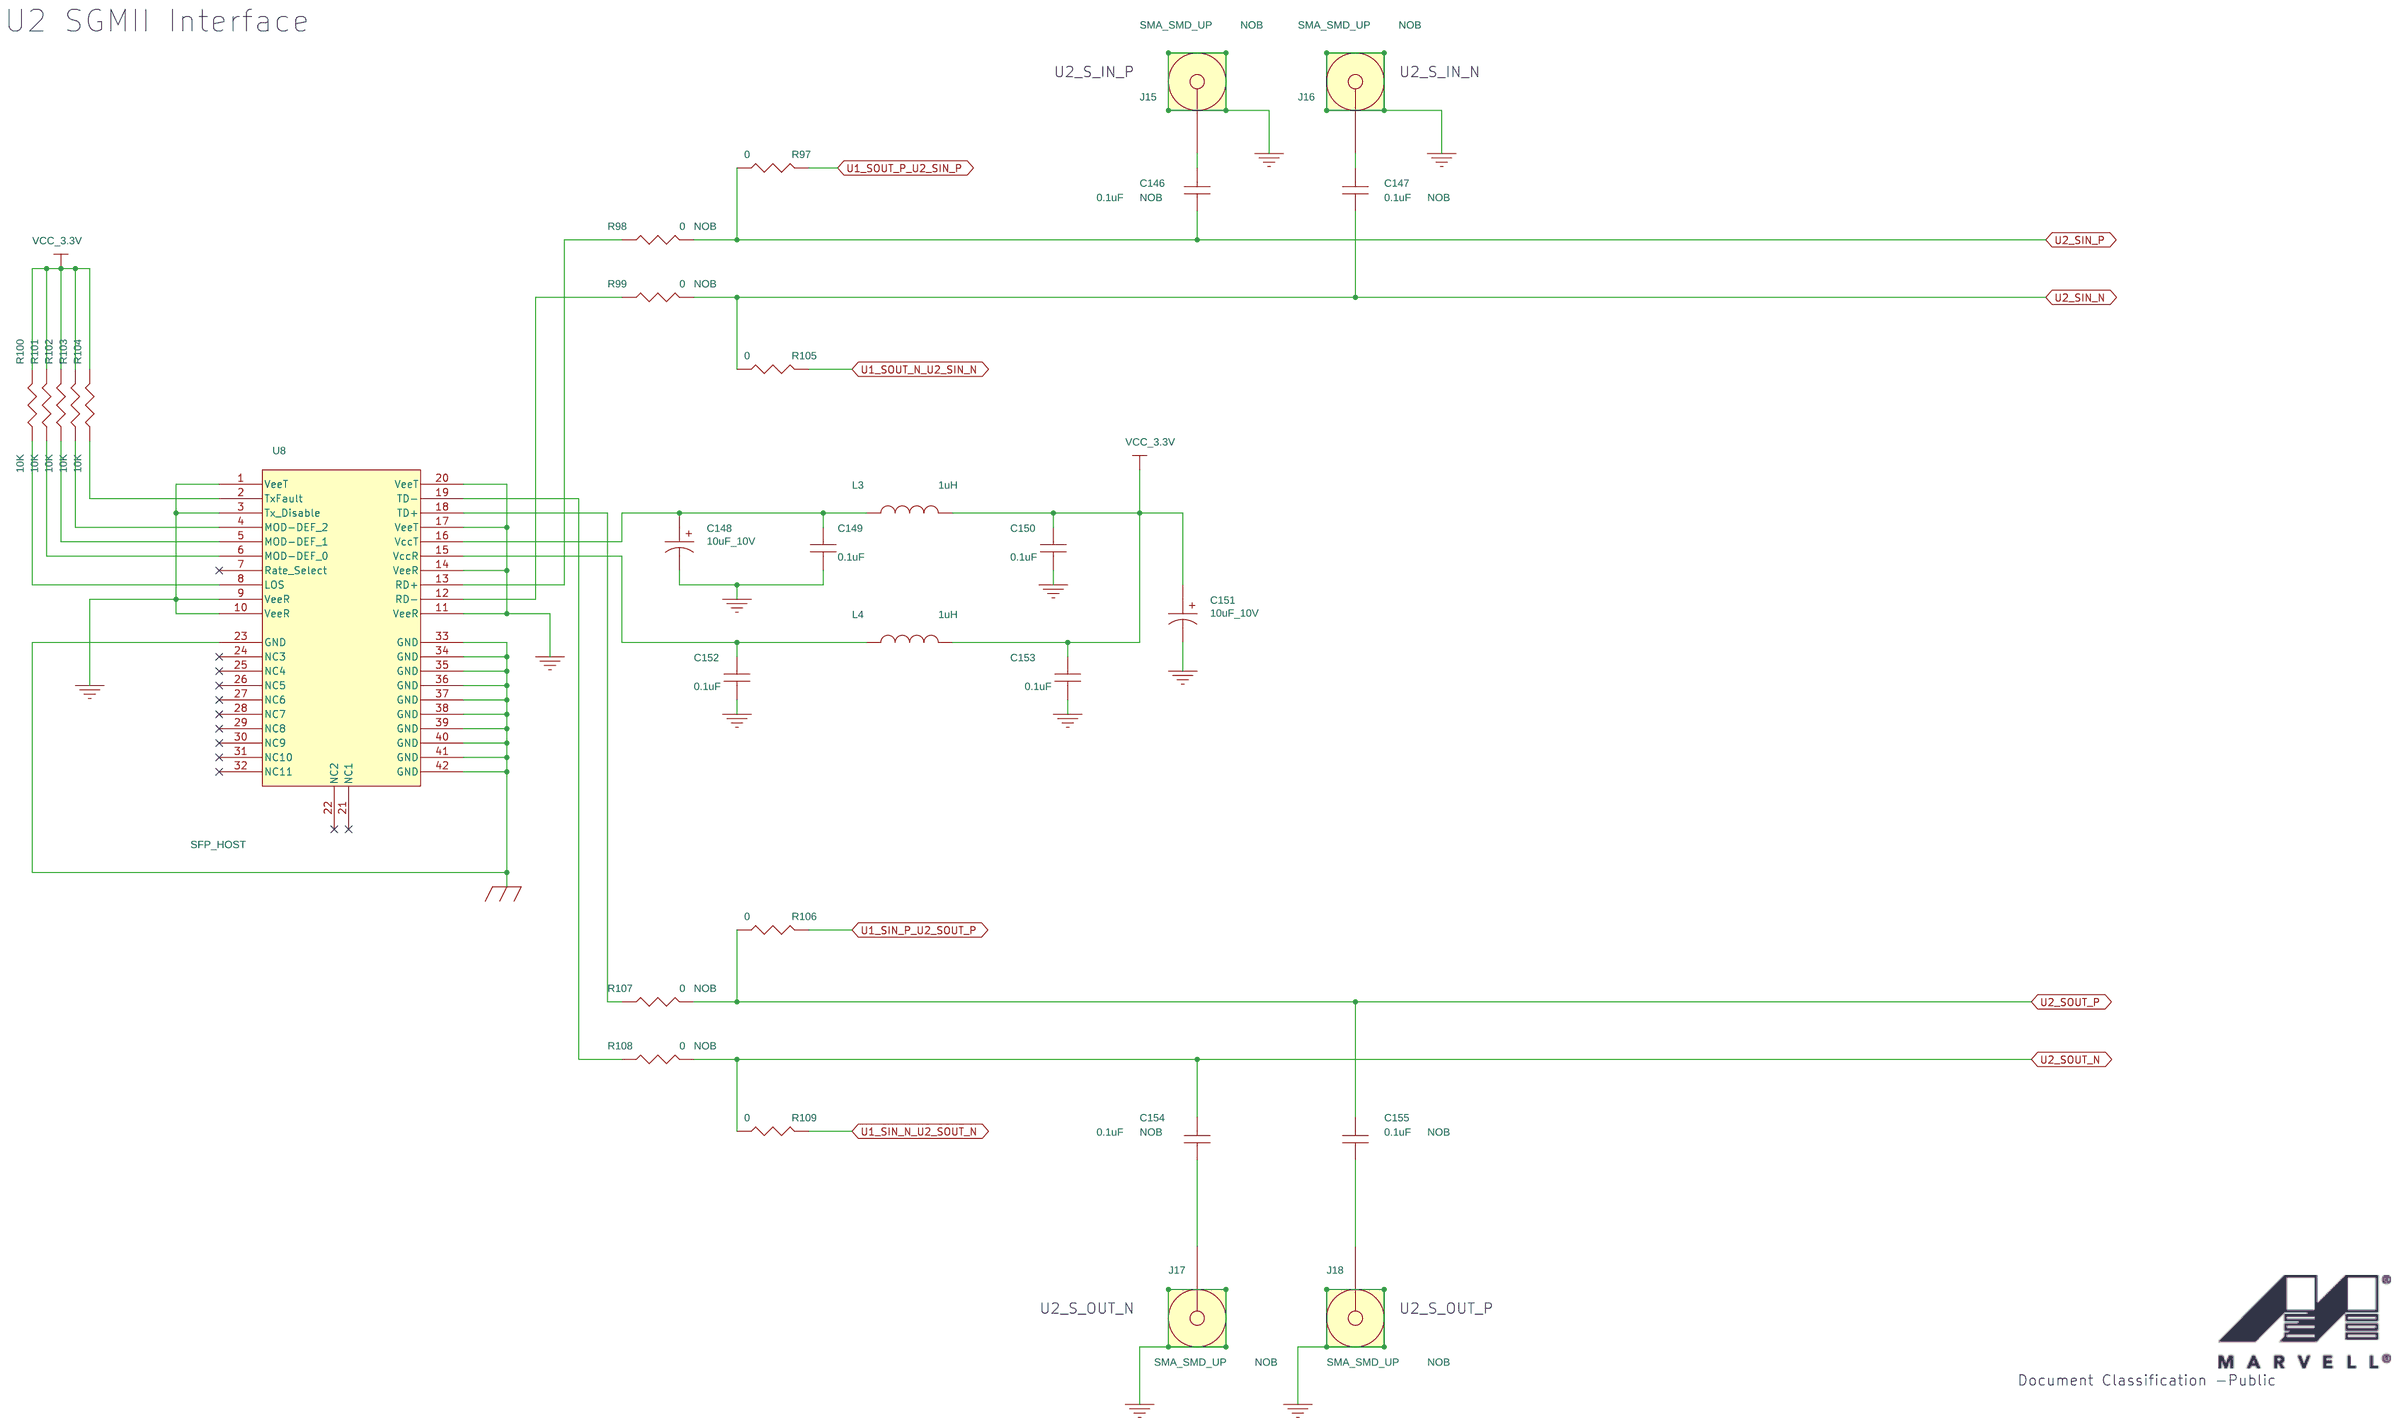
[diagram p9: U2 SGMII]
11 Power 1: size Custom
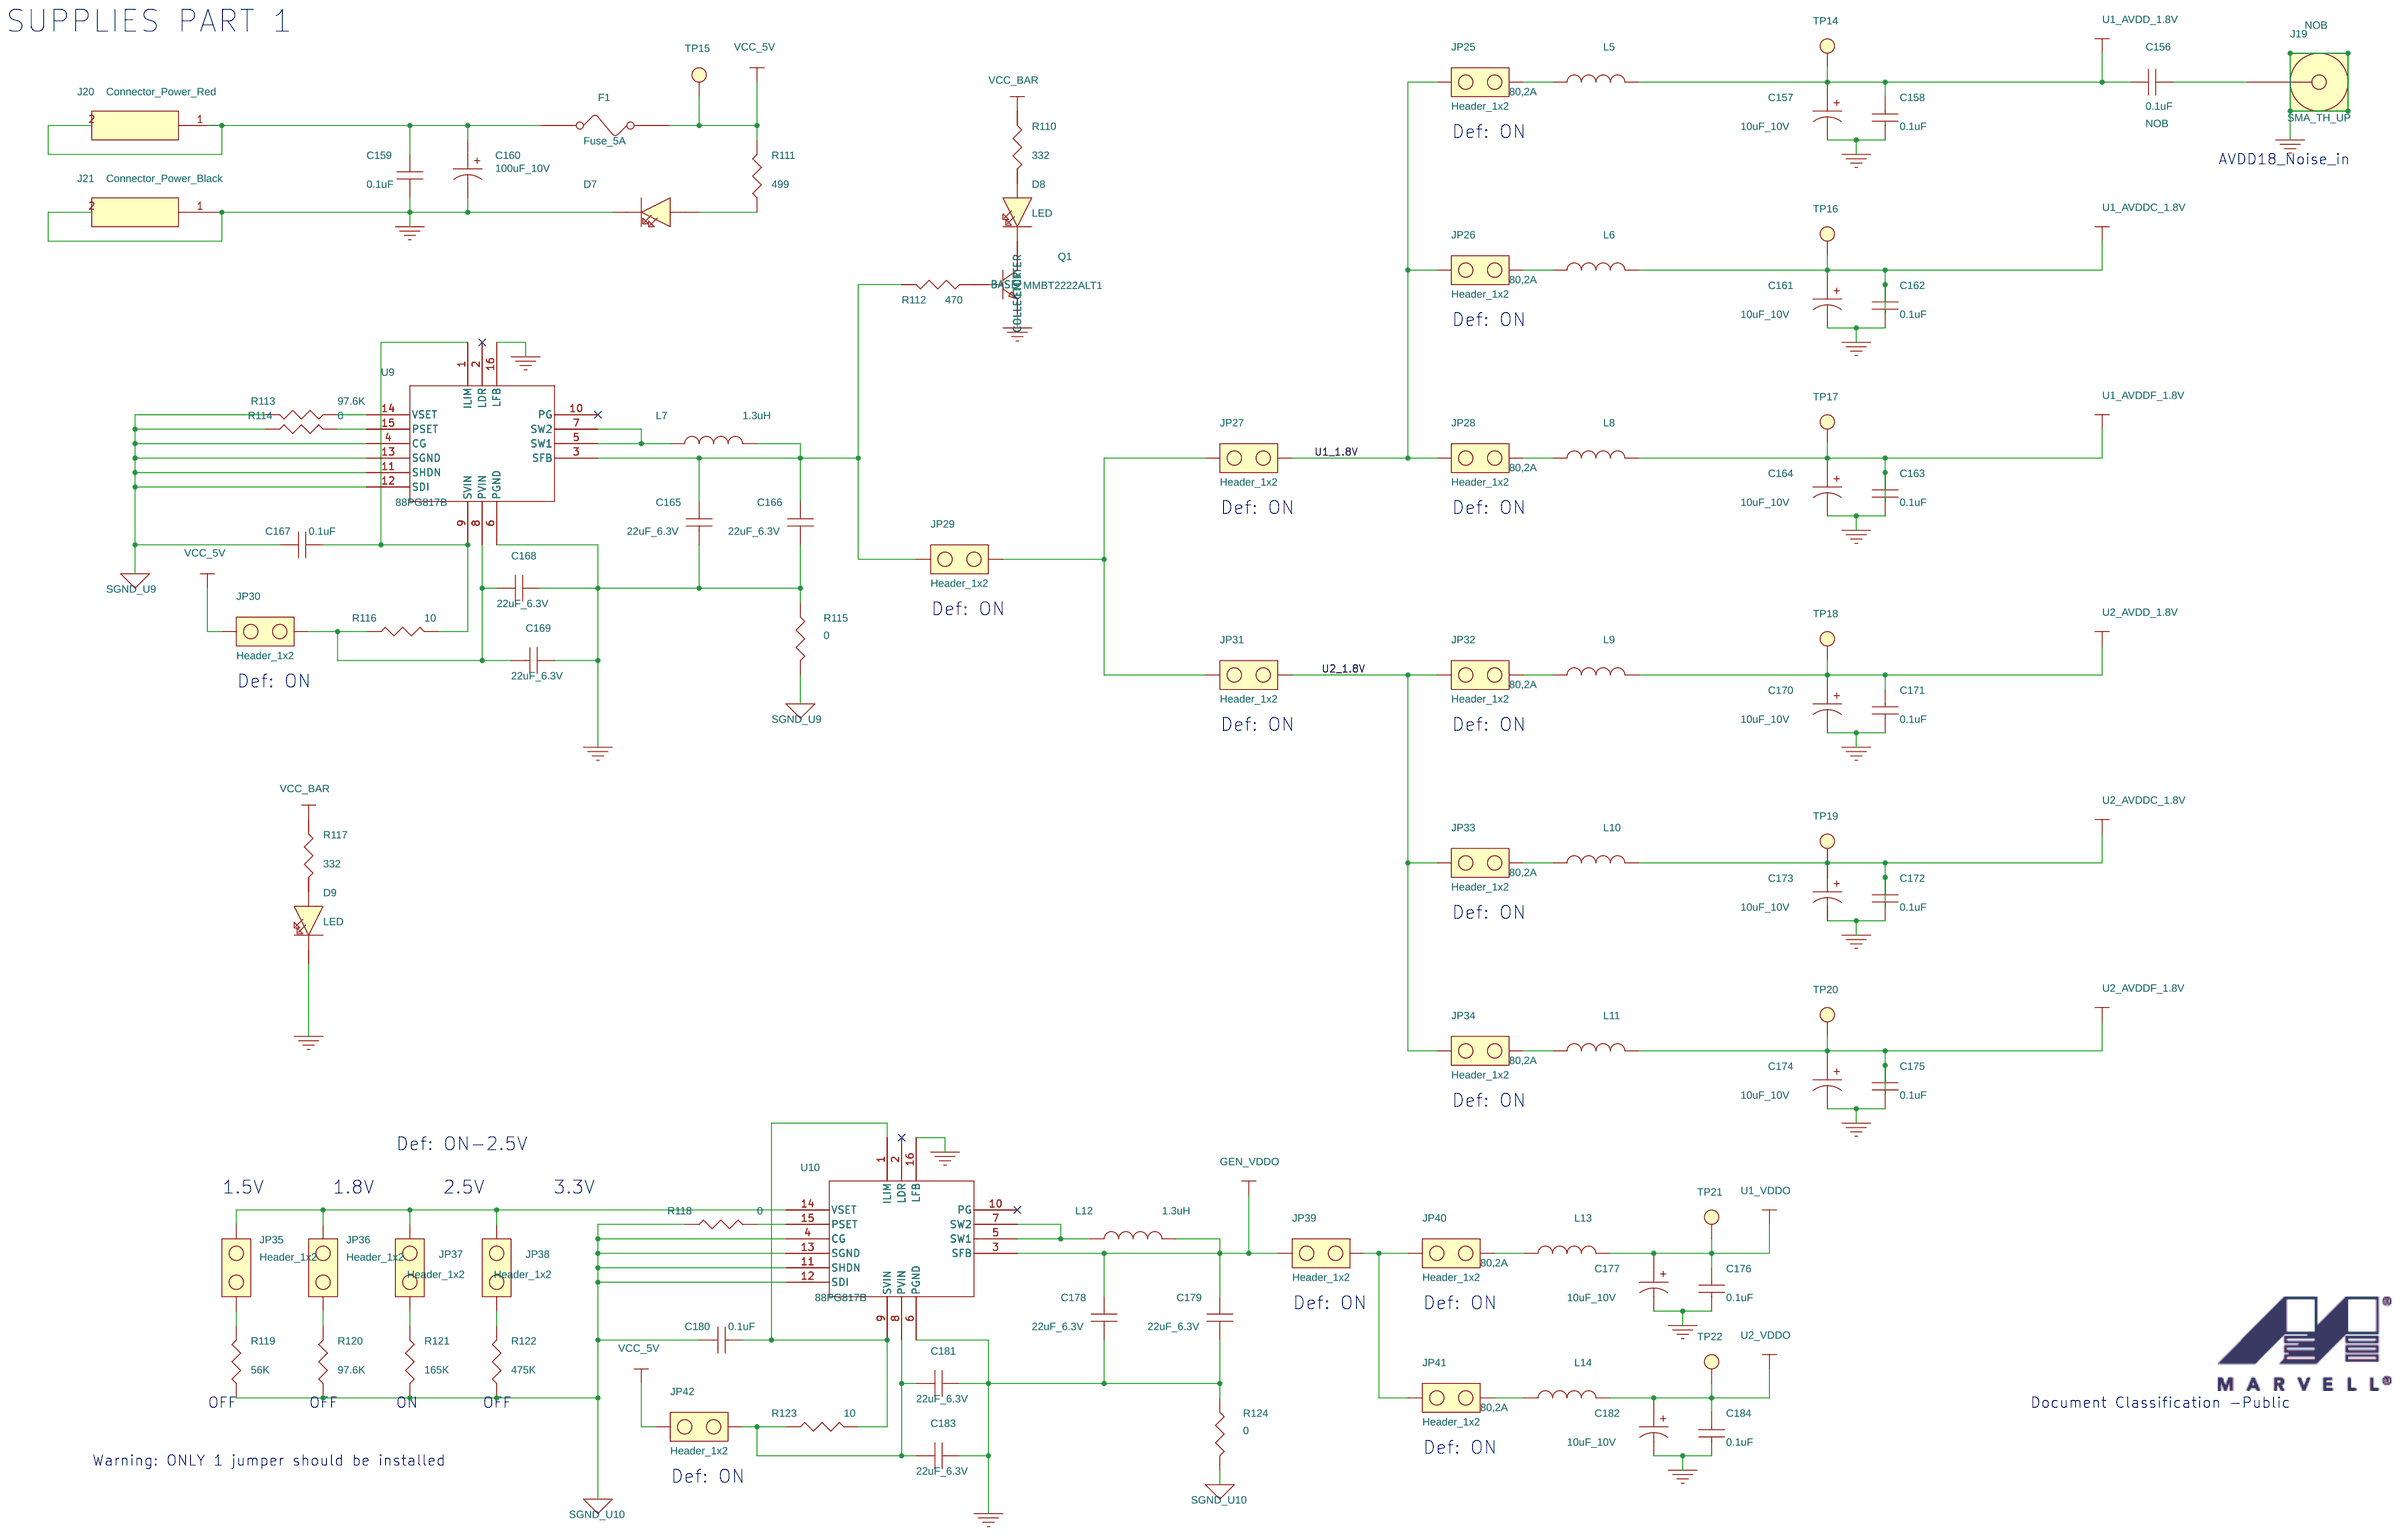
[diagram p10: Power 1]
12 Power 2: size Custom
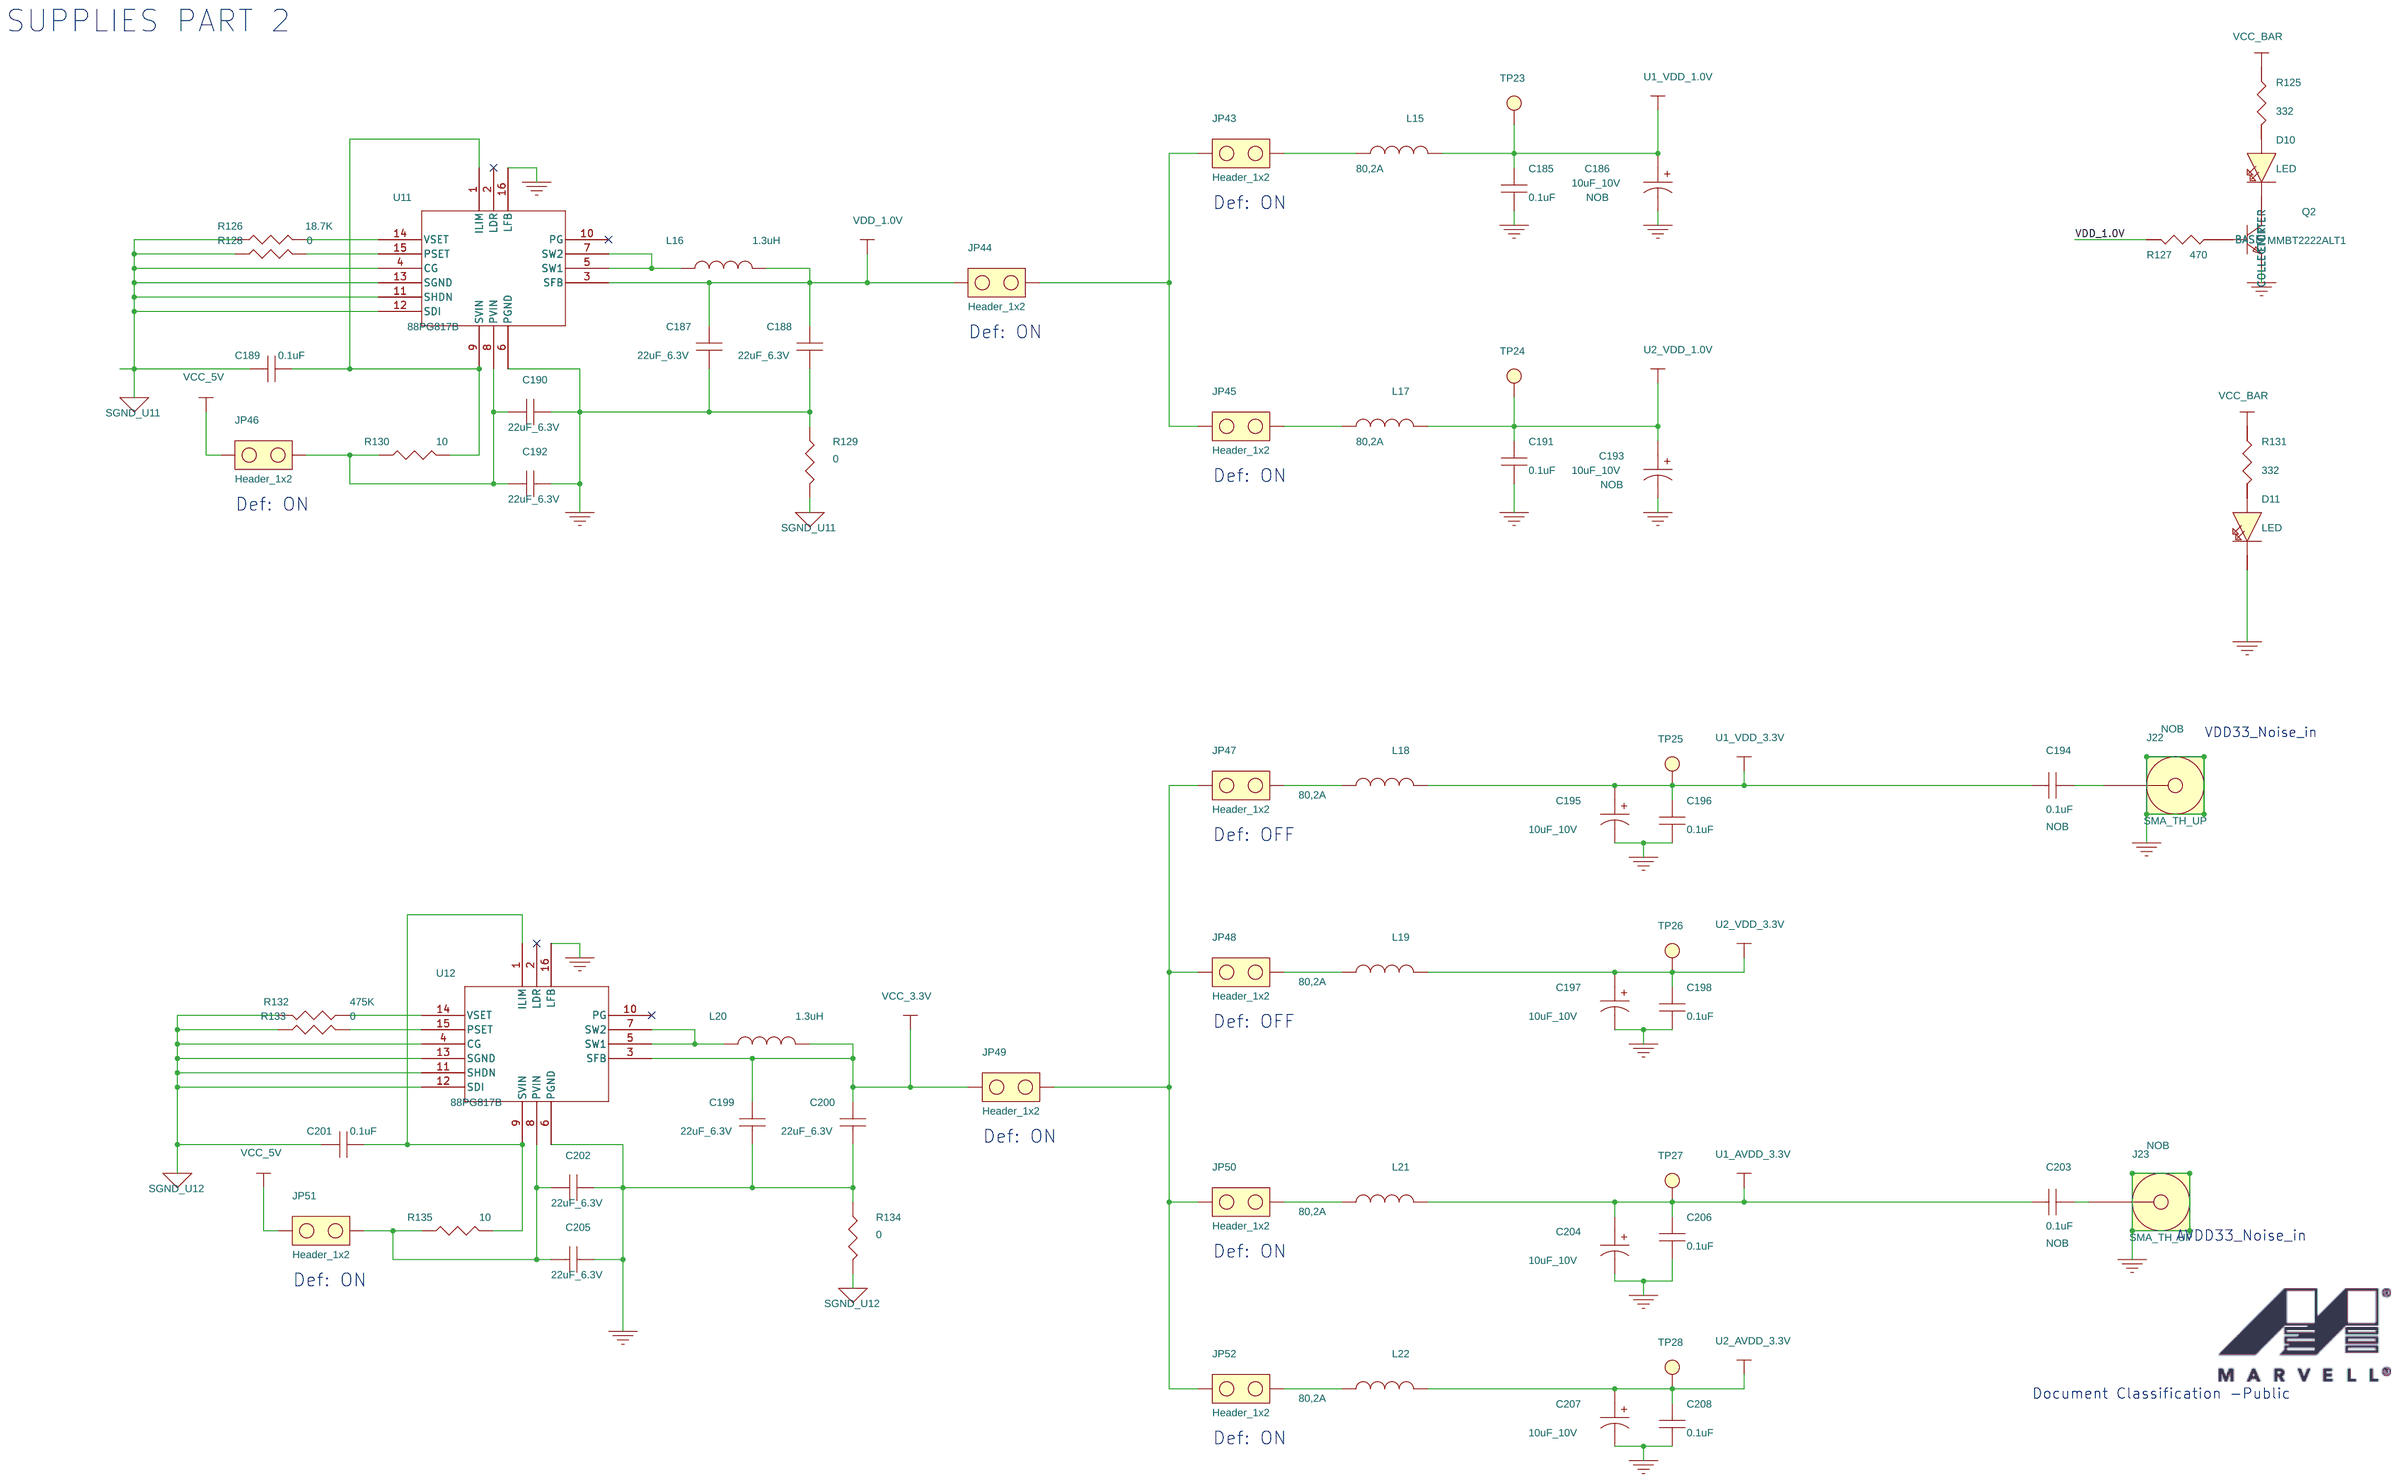
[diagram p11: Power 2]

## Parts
sheet 88E1512 - U1
C1  0.1uF  [0402]
C2  10uF_10V  [3216P]
C3  0.1uF  [0402]
C4  10uF_10V  [3216P]
C5  0.1uF  [0402]
C6  27pF  [0603]
C7  27pF  [0603]
C8  0.1uF  [0402]
C9  0.1uF  [0402]
C10  0.1uF  [0402]
C11  10uF_6.3V  [0805]
C12  4.7uF_6.3V  [0805]
C13  1uF  [0402]
C14  0.1uF  [0402]
C15  0.1uF  [0603]
C16  0.1uF  [0402]
C17  0.1uF  [0402]
C18  0.1uF  [0402]
C19  10uF_6.3V  [0805]
C20  4.7uF_6.3V  [0805]
C21  1uF  [0402]
C22  0.1uF  [0603]
C23  0.1uF  [0603]
C24  0.22uF  [0402]
C25  0.1uF  [0402]
C26  10uF_6.3V  [0805]
C27  4.7uF_6.3V  [0805]
C28  1uF  [0402]
C29  0.1uF  [0402]
C30  10uF_6.3V  [0805]
C31  4.7uF_6.3V  [0805]
C32  1uF  [0402]
C33  0.1uF  [0402]
C34  0.1uF  [0402]
C35  0.1uF  [0402]
C36  0.1uF  [0402]
C37  10uF_6.3V  [0805]
C38  10uF_6.3V  [0805]
C39  4.7uF_6.3V  [0805]
C40  1uF  [0402]
C41  0.1uF  [0402]
C42  0.1uF  [0402]
C43  0.1uF  [0402]
C44  10uF_6.3V  [0805]
C45  1uF  [0402]
C46  0.1uF  [0402]
C47  0.1uF  [0402]
C48  0.1uF  [0402]
C49  10uF_6.3V  [0805]
C50  1uF  [0402]
J1  SMA_TH_UP  [SMA5_TH_UP]
J2  SMA_TH_UP  [SMA5_TH_UP]
J3  SMA_TH_UP  [SMA5_TH_UP]
J4  SMA_TH_UP  [SMA5_TH_UP]
J5  SMA_TH_UP  [SMA5_TH_UP]
J6  SMA_TH_UP  [SMA5_TH_UP]
J7  SMA_TH_UP  [SMA5_TH_UP]
JP1  Header_1x2  [HDR_1X2]
JP2  Header_1x3  [HDR_1X3]
JP3  Header_2x2  [HDR_2X2]
JP4  Header_1x2  [HDR_1X2]
JP5  Header_1x2  [HDR_1X2]
JP6  Header_1x2  [HDR_1X2]
R1  4.7K  [0603]
R2  4.7K  [0603]
R3  0  [0603]
R4  22.1  [0603]
R5  0  [0603]
R6  0  [0603]
R8  4.99K  [0603]
R9  0  [0603]
R10  0  [0603]
R11  0  [0603]
R12  0  [0603]
R13  4.99K  [0603]
R14  49.9  [0603]
R15  49.9  [0603]
R16  0  [0603]
SKT1  SKT_QFN56_JT NEW EPAD size  [skt_qfn50p800x800x100-56n_jt_OC]
SW1  SW_PUSHBUTTON  [SWITCH_TACTILE]
TP1  Header_1x1  [HDR_1X1]
TP2  Header_1x1  [HDR_1X1]
TP3  Header_1x1  [HDR_1X1]
TP4  Header_1x1  [HDR_1X1]
TP5  Header_1x1  [HDR_1X1]
TP29  Header_1x1  [HDR_1X1]
U1  88E1512P_QFN56  [QFN50P800X800X100-56N_180X180EP]
U3  MAX6337US16D3-T  [SOT-143]
Y1  25MHZ OSC-SMD4_2.5V  [OSC4_SMD_7X5]
Y2  CRYSTAL_25MHz  [XTAL_V]
sheet 88E1512 - U2
C51  0.1uF  [0402]
C52  10uF_10V  [3216P]
C53  0.1uF  [0402]
C54  0.1uF  [0402]
C55  27pF  [0603]
C56  27pF  [0603]
C57  47pF  [0402]
C58  0.1uF  [0402]
C59  0.1uF  [0402]
C60  10uF_6.3V  [0805]
C61  10uF_6.3V  [0805]
C62  4.7uF_6.3V  [0805]
C63  0.1uF  [0402]
C64  1uF  [0402]
C65  0.1uF  [0402]
C66  0.1uF  [0402]
C67  0.1uF  [0402]
C68  10uF_6.3V  [0805]
C69  4.7uF_6.3V  [0805]
C70  1uF  [0402]
C71  0.22uF  [0402]
C72  0.1uF  [0402]
C73  10uF_6.3V  [0805]
C74  4.7uF_6.3V  [0805]
C75  1uF  [0402]
C76  0.1uF  [0402]
C77  10uF_6.3V  [0805]
C78  4.7uF_6.3V  [0805]
C79  1uF  [0402]
C80  0.1uF  [0402]
C81  0.1uF  [0402]
C82  0.1uF  [0402]
C83  0.1uF  [0402]
C84  10uF_6.3V  [0805]
C85  10uF_6.3V  [0805]
C86  4.7uF_6.3V  [0805]
C87  1uF  [0402]
C88  0.1uF  [0402]
C89  0.1uF  [0402]
C90  0.1uF  [0402]
C91  10uF_6.3V  [0805]
C92  1uF  [0402]
C93  0.1uF  [0402]
C94  0.1uF  [0402]
C95  0.1uF  [0402]
C96  10uF_6.3V  [0805]
C97  1uF  [0402]
J8  SMA_TH_UP  [SMA5_TH_UP]
J9  RJ11  [RJ-11_SH]
J10  SMA_TH_UP  [SMA5_TH_UP]
JP7  Header_1x2  [HDR_1X2]
JP8  Header_1x2  [HDR_1X2]
JP9  Header_1x2  [HDR_1X2]
JP10  Header_1x2  [HDR_1X2]
R17  0  [0603]
R18  22.1  [0603]
R19  0  [0603]
R20  0  [0603]
R21  0  [0603]
R22  1.5K  [0603]
R23  49.9  [0603]
R24  4.99K  [0603]
R25  4.99K  [0603]
R26  49.9  [0603]
R27  49.9  [0603]
SKT2  SKT_QFN56_JT NEW EPAD size  [skt_qfn50p800x800x100-56n_jt_OC]
TP6  Header_1x1  [HDR_1X1]
TP7  Header_1x1  [HDR_1X1]
TP8  Header_1x1  [HDR_1X1]
TP9  Header_1x1  [HDR_1X1]
TP10  Header_1x1  [HDR_1X1]
TP11  Header_1x1  [HDR_1X1]
TP12  Header_1x1  [HDR_1X1]
TP13  Header_1x1  [HDR_1X1]
U2  88E1512P_QFN56  [QFN50P800X800X100-56N_180X180EP]
U4  SN74LVC126A  [SOIC127P600X175-14AN]
Y3  25MHZ OSC-SMD4_2.5V  [OSC4_SMD_7X5]
Y4  CRYSTAL_25MHz  [XTAL_V]
sheet LEDs - Configuration
D1  LED  [1206_LED_DOT]
D2  LED  [1206_LED_DOT]
D3  LED  [1206_LED_DOT]
D4  LED  [1206_LED_DOT]
D5  LED  [1206_LED_DOT]
D6  LED  [1206_LED_DOT]
INTn_1  Header_1x1  [HDR_1X1]
INTn_2  Header_1x1  [HDR_1X1]
J28  SMA_TH_UP  [SMA5_TH_UP]
J29  SMA_TH_UP  [SMA5_TH_UP]
J30  SMA_TH_UP  [SMA5_TH_UP]
J31  SMA_TH_UP  [SMA5_TH_UP]
JP11  Header_2x4  [HDR_2X4]
JP12  Header_1x2  [HDR_1X2]
JP13  Header_2x4  [HDR_2X4]
JP14  Header_1x2  [HDR_1X2]
JP54  Header_1x2  [HDR_1X2]
JP56  Header_1x2  [HDR_1X2]
JP57  Header_1x2  [HDR_1X2]
JP58  Header_1x2  [HDR_1X2]
R28  316  [0603]
R29  316  [0603]
R30  316  [0603]
R31  316  [0603]
R32  316  [0603]
R33  316  [0603]
R145  4.7K  [0603]
R146  4.7K  [0603]
R147  4.7K  [0603]
R148  4.7K  [0603]
R149  0  [0603]
R150  0  [0603]
R163  0  [0603]
R164  0  [0603]
sheet Power 1
C156  0.1uF  [0603]
C157  10uF_10V  [3216P]
C158  0.1uF  [0402]
C159  0.1uF  [0402]
C160  100uF_10V  [7343P]
C161  10uF_10V  [3216P]
C162  0.1uF  [0402]
C163  0.1uF  [0402]
C164  10uF_10V  [3216P]
C165  22uF_6.3V  [0805]
C166  22uF_6.3V  [0805]
C167  0.1uF  [0402]
C168  22uF_6.3V  [0805]
C169  22uF_6.3V  [0805]
C170  10uF_10V  [3216P]
C171  0.1uF  [0402]
C172  0.1uF  [0402]
C173  10uF_10V  [3216P]
C174  10uF_10V  [3216P]
C175  0.1uF  [0402]
C176  0.1uF  [0402]
C177  10uF_10V  [3216P]
C178  22uF_6.3V  [0805]
C179  22uF_6.3V  [0805]
C180  0.1uF  [0402]
C181  22uF_6.3V  [0805]
C182  10uF_10V  [3216P]
C183  22uF_6.3V  [0805]
C184  0.1uF  [0402]
D7  LED  [1206_LED_DOT]
D8  LED  [1206_LED_DOT]
D9  LED  [1206_LED_DOT]
F1  Fuse_5A  [1206]
J19  SMA_TH_UP  [SMA5_TH_UP]
J20  Connector_Power_Red  [CON2_PWR_400]
J21  Connector_Power_Black  [CON2_PWR_400]
JP25  Header_1x2  [HDR_1X2]
JP26  Header_1x2  [HDR_1X2]
JP27  Header_1x2  [HDR_1X2]
JP28  Header_1x2  [HDR_1X2]
JP29  Header_1x2  [HDR_1X2]
JP30  Header_1x2  [HDR_1X2]
JP31  Header_1x2  [HDR_1X2]
JP32  Header_1x2  [HDR_1X2]
JP33  Header_1x2  [HDR_1X2]
JP34  Header_1x2  [HDR_1X2]
JP35  Header_1x2  [HDR_1X2]
JP36  Header_1x2  [HDR_1X2]
JP37  Header_1x2  [HDR_1X2]
JP38  Header_1x2  [HDR_1X2]
JP39  Header_1x2  [HDR_1X2]
JP40  Header_1x2  [HDR_1X2]
JP41  Header_1x2  [HDR_1X2]
JP42  Header_1x2  [HDR_1X2]
L5  80,2A  [1206]
L6  80,2A  [1206]
L7  1.3uH  [D62LCB]
L8  80,2A  [1206]
L9  80,2A  [1206]
L10  80,2A  [1206]
L11  80,2A  [1206]
L12  1.3uH  [D62LCB]
L13  80,2A  [1206]
L14  80,2A  [1206]
Q1  MMBT2222ALT1  [SOT-23_3_132]
R110  332  [0603]
R111  499  [0603]
R112  470  [0603]
R113  97.6K  [0603]
R114  0  [0603]
R115  0  [0603]
R116  10  [0603]
R117  332  [0603]
R118  0  [0603]
R119  56K  [0603]
R120  97.6K  [0603]
R121  165K  [0603]
R122  475K  [0603]
R123  10  [0603]
R124  0  [0603]
TP14  Header_1x1  [HDR_1X1]
TP15  Header_1x1  [HDR_1X1]
TP16  Header_1x1  [HDR_1X1]
TP17  Header_1x1  [HDR_1X1]
TP18  Header_1x1  [HDR_1X1]
TP19  Header_1x1  [HDR_1X1]
TP20  Header_1x1  [HDR_1X1]
TP21  Header_1x1  [HDR_1X1]
TP22  Header_1x1  [HDR_1X1]
U9  88PG817B  [QFN50P300X300X100-16N]
U10  88PG817B  [QFN50P300X300X100-16N]
sheet Power 2
C185  0.1uF  [0402]
C186  10uF_10V  [3216P]
C187  22uF_6.3V  [0805]
C188  22uF_6.3V  [0805]
C189  0.1uF  [0402]
C190  22uF_6.3V  [0805]
C191  0.1uF  [0402]
C192  22uF_6.3V  [0805]
C193  10uF_10V  [3216P]
C194  0.1uF  [0603]
C195  10uF_10V  [3216P]
C196  0.1uF  [0402]
C197  10uF_10V  [3216P]
C198  0.1uF  [0402]
C199  22uF_6.3V  [0805]
C200  22uF_6.3V  [0805]
C201  0.1uF  [0402]
C202  22uF_6.3V  [0805]
C203  0.1uF  [0603]
C204  10uF_10V  [3216P]
C205  22uF_6.3V  [0805]
C206  0.1uF  [0402]
C207  10uF_10V  [3216P]
C208  0.1uF  [0402]
D10  LED  [1206_LED_DOT]
D11  LED  [1206_LED_DOT]
J22  SMA_TH_UP  [SMA5_TH_UP]
J23  SMA_TH_UP  [SMA5_TH_UP]
JP43  Header_1x2  [HDR_1X2]
JP44  Header_1x2  [HDR_1X2]
JP45  Header_1x2  [HDR_1X2]
JP46  Header_1x2  [HDR_1X2]
JP47  Header_1x2  [HDR_1X2]
JP48  Header_1x2  [HDR_1X2]
JP49  Header_1x2  [HDR_1X2]
JP50  Header_1x2  [HDR_1X2]
JP51  Header_1x2  [HDR_1X2]
JP52  Header_1x2  [HDR_1X2]
L15  80,2A  [1206]
L16  1.3uH  [D62LCB]
L17  80,2A  [1206]
L18  80,2A  [1206]
L19  80,2A  [1206]
L20  1.3uH  [D62LCB]
L21  80,2A  [1206]
L22  80,2A  [1206]
Q2  MMBT2222ALT1  [SOT-23_3_132]
R125  332  [0603]
R126  18.7K  [0603]
R127  470  [0603]
R128  0  [0603]
R129  0  [0603]
R130  10  [0603]
R131  332  [0603]
R132  475K  [0603]
R133  0  [0603]
R134  0  [0603]
R135  10  [0603]
TP23  Header_1x1  [HDR_1X1]
TP24  Header_1x1  [HDR_1X1]
TP25  Header_1x1  [HDR_1X1]
TP26  Header_1x1  [HDR_1X1]
TP27  Header_1x1  [HDR_1X1]
TP28  Header_1x1  [HDR_1X1]
U11  88PG817B  [QFN50P300X300X100-16N]
U12  88PG817B  [QFN50P300X300X100-16N]
sheet RGMII LB OPTION
J24  SMA_TH_UP  [SMA5_TH_UP]
J25  SMA_TH_UP  [SMA5_TH_UP]
J26  SMA_TH_UP  [SMA5_TH_UP]
J27  SMA_TH_UP  [SMA5_TH_UP]
JP23  Header_2X6  [HDR_2X6]
JP24  Header_2X6  [HDR_2X6]
JP53  Header_2X6  [HDR_2X6]
JP55  Header_2X6  [HDR_2X6]
R136  0  [0603]
R137  0  [0603]
R138  0  [0603]
R139  0  [0603]
R140  0  [0603]
R141  0  [0603]
R142  0  [0603]
R143  0  [0603]
R151  4.7K  [0603]
R152  4.7K  [0603]
R153  4.7K  [0603]
R154  4.7K  [0603]
R155  4.7K  [0603]
R156  4.7K  [0603]
R157  4.7K  [0603]
R158  4.7K  [0603]
R159  4.7K  [0603]
R160  4.7K  [0603]
R161  4.7K  [0603]
R162  4.7K  [0603]
sheet U1 Copper Media
C98  1uF_100V  [1812]
C99  47.3nF_2KV  [1812]
C100  1uF_100V  [1812]
C101  47.3nF_2KV  [1812]
C102  10nF  [0402]
C103  0.1uF  [0402]
C104  1000pF  [0402]
C105  1000p_3KV  [1812]
C106  1000pF  [0402]
C107  0.1uF  [0402]
C108  10nF  [0402]
C109  1000p_3KV  [1812]
C110  0.1uF  [0402]
C111  10nF  [0402]
C112  1000pF  [0402]
C113  1000p_3KV  [1812]
C114  0.1uF  [0402]
C115  10nF  [0402]
C116  1000pF  [0402]
C117  1000p_3KV  [1812]
C118  1uF_100V  [1812]
C119  47.3nF_2KV  [1812]
C120  1uF_100V  [1812]
C121  47.3nF_2KV  [1812]
C122  1000p_3KV  [1812]
C123  1000p_3KV  [1812]
CON1  RJ45_1000BASETX  [RJ-45_GIG_RA_SH2]
JP15  Header_1x2  [HDR_1X2]
JP16  Header_1x2  [HDR_1X2]
JP17  Header_1x2  [HDR_1X2]
JP18  Header_1x2  [HDR_1X2]
R34  1.5  [1206]
R35  1.5  [1206]
R36  0  [0603]
R37  100  [0603]
R38  75_1/8W  [R1_8W]
R39  0  [0603]
R40  0  [0603]
R41  0  [0603]
R42  0  [0603]
R43  0  [0603]
R44  100  [0603]
R45  0  [0603]
R46  75_1/8W  [R1_8W]
R47  0  [0603]
R48  0  [0603]
R49  0  [0603]
R50  100  [0603]
R51  0  [0603]
R52  75_1/8W  [R1_8W]
R53  0  [0603]
R54  0  [0603]
R55  0  [0603]
R56  100  [0603]
R57  0  [0603]
R58  75_1/8W  [R1_8W]
R59  0  [0603]
R60  1.5  [1206]
R61  1.5  [1206]
R62  10M  [0603]
R63  10M  [0603]
U5  H5007B  [SOIC50P1600X551-24N]
sheet U1 SGMII
C136  0.1uF  [0603]
C137  0.1uF  [0603]
C138  10uF_10V  [3216P]
C139  0.1uF  [0603]
C140  0.1uF  [0603]
C141  10uF_10V  [3216P]
C142  0.1uF  [0603]
C143  0.1uF  [0603]
C144  0.1uF  [0603]
C145  0.1uF  [0603]
J11  SMA_SMD_UP  [SMA5_SMD_UP]
J12  SMA_SMD_UP  [SMA5_SMD_UP]
J13  SMA_SMD_UP  [SMA5_SMD_UP]
J14  SMA_SMD_UP  [SMA5_SMD_UP]
L1  1uH  [1206]
L2  1uH  [1206]
R84  0  [0603]
R85  0  [0603]
R86  0  [0603]
R87  0  [0603]
R88  10K  [0603]
R89  10K  [0603]
R90  10K  [0603]
R91  10K  [0603]
R92  10K  [0603]
R93  0  [0603]
R94  0  [0603]
R95  0  [0603]
R96  0  [0603]
U7  SFP_HOST  [sfp_host]
sheet U2 Copper Media
C124  0.1uF  [0402]
C125  10nF  [0402]
C126  1000pF  [0402]
C127  0.1uF  [0402]
C128  10nF  [0402]
C129  1000pF  [0402]
C130  0.1uF  [0402]
C131  10nF  [0402]
C132  1000pF  [0402]
C133  0.1uF  [0402]
C134  10nF  [0402]
C135  1000pF  [0402]
JP19  Header_1x2  [HDR_1X2]
JP20  Header_1x2  [HDR_1X2]
JP21  Header_1x2  [HDR_1X2]
JP22  Header_1x2  [HDR_1X2]
R64  0  [0603]
R65  0  [0603]
R66  100  [0603]
R67  0  [0603]
R68  0  [0603]
R69  0  [0603]
R70  0  [0603]
R71  100  [0603]
R72  0  [0603]
R73  0  [0603]
R74  0  [0603]
R75  0  [0603]
R76  100  [0603]
R77  0  [0603]
R78  0  [0603]
R79  0  [0603]
R80  0  [0603]
R81  100  [0603]
R82  0  [0603]
R83  0  [0603]
U6  0826-1G1T-43-F  [RJ45-MAG_1X1_BEL_LED]
sheet U2 SGMII
C146  0.1uF  [0603]
C147  0.1uF  [0603]
C148  10uF_10V  [3216P]
C149  0.1uF  [0603]
C150  0.1uF  [0603]
C151  10uF_10V  [3216P]
C152  0.1uF  [0603]
C153  0.1uF  [0603]
C154  0.1uF  [0603]
C155  0.1uF  [0603]
J15  SMA_SMD_UP  [SMA5_SMD_UP]
J16  SMA_SMD_UP  [SMA5_SMD_UP]
J17  SMA_SMD_UP  [SMA5_SMD_UP]
J18  SMA_SMD_UP  [SMA5_SMD_UP]
L3  1uH  [1206]
L4  1uH  [1206]
R97  0  [0603]
R98  0  [0603]
R99  0  [0603]
R100  10K  [0603]
R101  10K  [0603]
R102  10K  [0603]
R103  10K  [0603]
R104  10K  [0603]
R105  0  [0603]
R106  0  [0603]
R107  0  [0603]
R108  0  [0603]
R109  0  [0603]
U8  SFP_HOST  [sfp_host]

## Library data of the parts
C1 C5 C8-C10 C16-C18 C24 C25 C29 C33-C36 C41-C43 C46-C48 C51 C53 C58 C59 C65-C67 C71 C72 C76 C80-C83 C88-C90 C93-C95 C103 C107 C110 C114 C124 C127 C130 C133 C158 C159 C162 C163 C167 C171 C172 C175 C176 C180 C184 C185 C189 C191 C196 C198 C201 C206 C208 = CAP_NP: Part Number: GRM155R71H104KE14D
C2 C4 C52 C138 C141 C148 C151 C157 C161 C164 C170 C173 C174 C177 C182 C195 C197 C204 C207 = CAP_P: Assembly Footprint: case_A; Part Number: T491A106K010AT
C3 C14 C54 C63 = CAP_NP: Part Number: GRM155R71H104KE14D; Stuff Option: NOB
C6 C7 C55 C56 = CAP_NP: Part Number: GRM1885C1H270JA01D, CGA3E2C0G1H270J080AA
C11 C19 C26 C30 C37 C38 C44 C49 C60 C61 C68 C73 C77 C84 C85 C91 C96 = CAP_NP: Part Number: GRM21BR70J106KE76L
C12 C20 C27 C31 C39 C62 C69 C74 C78 C86 = CAP_NP: Part Number: GRM21BR60J475KA11L,C2012X5R0J475KT
C13 C21 C28 C32 C40 C45 C50 C64 C70 C75 C79 C87 C92 C97 = CAP_NP: Part Number: GRM155R61A105KE15D
C15 C22 C136 C137 C144-C147 C154-C156 C194 C203 = CAP_NP: Part Number: GRM188R71H104KA93D; Stuff Option: NOB
C23 C139 C140 C142 C143 C149 C150 C152 C153 = CAP_NP: Part Number: GRM188R71H104KA93D
J1-J8 J10 J19 J22-J31 = SMA_TH_UP: Assembly Footprint: T/H; Part Number: Johnson 142-0701-201; Stuff Option: NOB
JP1 JP7 JP15-JP22 = JUMPER_1X2_VERTICAL: Assembly Footprint: 100Mil_T/H; Part Number: BPEG40SS-GBR_1x2, TSW-150-23-G-S; Stuff Option: NOB
JP2 = HEADER_1x3: Assembly Footprint: 100Mil_T/H; Part Number: BPEG40SS-GBR_1x3, TSW-150-23-G-S
JP3 = HEADER_2X2: Assembly Footprint: 100Mil_T/H; Part Number: BPEG80DS-GBR_2x2, TSW-150-23-G-D
JP4-JP6 JP8-JP10 JP12 JP14 JP25-JP52 JP54 JP56-JP58 = JUMPER_1X2_VERTICAL: Assembly Footprint: 100Mil_T/H; Part Number: BPEG40SS-GBR_1x2, TSW-150-23-G-S
R1 R2 R145-R148 R151-R162 = R: Part Number: NRC06J472TRF
R3 R16 R17 R39 R40 R42 R47 R48 R53 R54 R59 R64 R68 R69 R73 R74 R78 R79 R83 R85 R86 R94 R95 R98 R99 R107 R108 R136-R139 R149 R150 R163 R164 = R: Part Number: RK73Z1JTTD; Stuff Option: NOB
R4 R18 = R: Part Number: NRC06F22R1TRF; Stuff Option: NOB
R5 R6 R9 R11 R12 R19-R21 R36 R41 R43 R45 R49 R51 R55 R57 R65 R67 R70 R72 R75 R77 R80 R82 R84 R87 R93 R96 R97 R105 R106 R109 R114 R115 R118 R124 R128 R129 R133 R134 R140-R143 = R: Part Number: RK73Z1JTTD
R8 R13 R24 R25 = R: Part Number: RK73H1JTTD4991F
R10 = R: Part Number: RK73Z1JTTD; STUFF OPTION: NOB
R14 R15 R23 R26 R27 = R: Part Number: RK73H1JTTD49R9F
SKT1 SKT2 = SKT_QFN56_JT_NEW_EPAD_size: Assembly Footprint: QFN56 Socket; Part Number: JTI-TS56QFN-8.0X8.0-0.50-9153-0001
SW1 = SW_PUSHBUTTON: Assembly Footprint: SMD; Part Number: 101-0267EV
INTn_1 INTn_2 TP1-TP28 = T_POINT_R: Assembly Footprint: 100Mil_T/H; Part Number: BPEG40SS-GBR_1x1, TSW-150-23-G-S
TP29 = T_POINT_R: Assembly Footprint: 100Mil_T/H; Part Number: BPEG40SS-GBR_1x1, TSW-150-23-G-S; Stuff Option: NOB
U1 U2 = 88E1512P_QFN56: Assembly Footprint: QFN56; Part Number: 88E1512PB2-NNP2C00
U3 = MAX6337: Assembly Footprint: SOT143-4
Y1 Y3 = OSC4_SMD_7X5: Part Number: 7W25070014,KC7050A25.000C20E00, O_25,0-JO75-B-2,5-1-LF, C67-50-17-25.000-T-2.5-R,DS0751SR_ZL03373; Stuff Option: NOB
Y2 Y4 = CRYSTAL_25MHZ: Assembly Footprint: T/H; Part Number: HC49SFWA25000P0HBQZZ, Q25,0-SS4-18-30/50-FU-LF,ZL03190,9B25070009,
C57 = CAP_NP: Part Number: NMC0402NPO470J50TRPF
J9 = RJ11: Assembly Footprint: T/H; Part Number: 5555154-1
R22 = R: Part Number: RMC1/16W8078651.5K
U4 = SN74LVC126A: Assembly Footprint: SOIC14; Part Number: 74LVC126AD
D1-D11 = LED: Assembly Footprint: 1206; Part Number: AP3216SGC,SML-LX1206GC-TR
JP11 JP13 = HEADER_2x4: Assembly Footprint: 100Mil_T/H; Part Number: BPEG80DS-GBR_2x4, TSW-150-23-G-D
R28-R33 = R: Part Number: RK73H1JLTD3160F
C160 = CAP_P: Assembly Footprint: D; Part Number: ECASD91A107M010K00
C165 C166 C168 C169 C178 C179 C181 C183 C187 C188 C190 C192 C199 C200 C202 C205 = CAP_NP: Part Number: GRM21BR60J226ME39L,JMK212BJ226MG-T
F1 = Fuse: Part Number: 429005WR,0466005.NR; PartNumber: Littlefuse 1206 Fast Acting 5A
J20 = Johnson_Plug: Assembly Footprint: T/H; Part Number: 1050752001
J21 = Johnson_Plug: Assembly Footprint: T/H; Part Number: 1050753001
L5 L6 L8-L11 L13-L15 L17-L19 L21 L22 = INDUCTOR: Part Number: CZP2BFLTE800M, HCB20-800-RC,BLM31PG121SN1D
L7 L12 L16 L20 = INDUCTOR: Part Number: A918BY-1R3N
Q1 Q2 = MMBT2222ALT1: Assembly Footprint: SOT23
R110 R117 R125 R131 = R: Part Number: RK73H1JTTD3320F
R111 = R: Part Number: RK73H1JTTD4990F
R112 R127 = R: Part Number: RK73H1JTTD4700F
R113 R120 = R: Part Number: RK73H1JTTD9762F
R116 R123 R130 R135 = R: Part Number: RK73H1JTTD10R0F
R119 = R: Part Number: RM06F5602CT
R121 = R: Part Number: RK73H1JTTD1653F
R122 R132 = R: Part Number: RM06F4753CT
U9-U12 = 88PG8x7B-QFN16: Assembly Footprint: QFN16; Part Number: 88PG817BB0-NAM1C000
C186 C193 = CAP_P: Assembly Footprint: case_A; Part Number: T491A106K010AT; Stuff Option: NOB
R126 = R: Part Number: ERJ-3EKF1872V
JP23 JP24 JP53 JP55 = HEADER_2X6: Assembly Footprint: 100Mil_T/H; Part Number: BPEG80DS-GBR_2x6, TSW-150-23-G-D
C98 C100 C118 C120 = CAP_NP: Part Number: 1812X105K101SNT; Stuff Option: NOB
C99 C101 C119 C121 = CAP_NP: Part Number: 1812X473K202SNT; Stuff Option: NOB
C102 C108 C111 C115 C125 C128 C131 C134 = CAP_NP: Part Number: GRM155R71H103KA88D
C104 C106 C112 C116 C126 C129 C132 C135 = CAP_NP: Part Number: GRM155R71H102KA01D, GMC04X7R102K50NTLF
C105 C109 C113 C117 C122 C123 = CAP_NP: Part Number: 1812X102K302SNT
CON1 = RJ45_1000BASETX: Assembly Footprint: T/H; Part Number: 44050-0002
R34 R35 R60 R61 = R: Part Number: RK73H2BTTD1R50F; Stuff Option: NOB
R37 R44 R50 R56 = R: Part Number: RK73H1JTTD1000F; Stuff Option: NOB
R38 R46 R52 R58 = R: Assembly Footprint: T/H; Part Number: CF1/8 75OHM 5% TR
R62 R63 = R: Part Number: RK73H1JTTD1005F
U5 = H5007B: Assembly Footprint: SOIC24; Display Value: H5007; Part Number: S558-5999-BZ,H5007B, H5070NL,LDM-S24E-G332
J11-J18 = SMA_SMD_UP: Assembly Footprint: SMD; Part Number: 142-0711-201, 73251-1350; Stuff Option: NOB
L1-L4 = INDUCTOR: Part Number: GLF32161R0KTLF
R88-R92 R100-R104 = R: Part Number: RK73H1JTTD1002F
U7 U8 = SFP_HOST: Assembly Footprint: SMD/T_H; Part Number: Molex_74441-0001, TYCO_1658524-1,Palconn_SFP-R-8270000011000,Palconn_SFP-R-8281110000001
R66 R71 R76 R81 = R: Part Number: RK73H1JTTD1000F
U6 = 0826-1G1T-43-F: Assembly Footprint: T/H

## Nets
GND: C1.2 C2.2 C3.2 C4.2 C5.2 C6.2 C7.2 C8.2 C9.2 C10.2 C11.2 C12.2 C13.2 C14.2 C16.2 C17.2 C18.2 C19.2 C20.2 C21.2 C25.2 C26.2 C27.2 C28.2 C29.2 C30.2 C31.2 C32.2 C33.2 C34.2 C35.2 C36.2 C37.2 C38.2 C39.2 C40.2 C41.2 C42.2 C43.2 C44.2 C45.2 C46.2 C47.2 C48.2 C49.2 C50.2 C51.2 C52.2 C53.2 C54.2 C55.2 C56.2 C57.2 C58.2 C59.2 C60.2 C61.2 C62.2 C63.2 C64.2 C65.2 C66.2 C67.2 C68.2 C69.2 C70.2 C72.2 C73.2 C74.2 C75.2 C76.2 C77.2 C78.2 C79.2 C80.2 C81.2 C82.2 C83.2 C84.2 C85.2 C86.2 C87.2 C88.2 C89.2 C90.2 C91.2 C92.2 C93.2 C94.2 C95.2 C96.2 C97.2 C102.2 C103.2 C104.2 C106.2 C107.2 C108.2 C110.2 C111.2 C112.2 C114.2 C115.2 C116.2 C122.1 C123.1 C124.2 C125.2 C126.2 C127.2 C128.2 C129.2 C130.2 C131.2 C132.2 C133.2 C134.2 C135.2 C138.2 C139.2 C140.2 C141.2 C142.2 C143.2 C148.2 C149.2 C150.2 C151.2 C152.2 C153.2 C157.2 C158.2 C159.2 C160.2 C161.2 C162.2 C163.2 C164.2 C165.2 C166.2 C168.1 C169.1 C170.2 C171.2 C172.2 C173.2 C174.2 C175.2 C176.2 C177.2 C178.2 C179.2 C181.1 C182.2 C183.1 C184.2 C185.2 C186.2 C187.2 C188.2 C190.1 C191.2 C192.1 C193.2 C195.2 C196.2 C197.2 C198.2 C199.2 C200.2 C202.1 C204.2 C205.1 C206.2 C207.2 C208.2 D7.2 D9.2 D11.2 J1.2 J1.3 J1.4 J1.5 J2.2 J2.3 J2.4 J2.5 J3.2 J3.3 J3.4 J3.5 J4.2 J4.3 J4.4 J4.5 J5.2 J5.3 J5.4 J5.5 J6.2 J6.3 J6.4 J6.5 J7.2 J7.3 J7.4 J7.5 J8.2 J8.3 J8.4 J8.5 J9.3 J9.4 J10.2 J10.3 J10.4 J10.5 J11.2 J11.3 J11.4 J11.5 J12.2 J12.3 J12.4 J12.5 J13.2 J13.3 J13.4 J13.5 J14.2 J14.3 J14.4 J14.5 J15.2 J15.3 J15.4 J15.5 J16.2 J16.3 J16.4 J16.5 J17.2 J17.3 J17.4 J17.5 J18.2 J18.3 J18.4 J18.5 J19.2 J19.3 J19.4 J19.5 J21.1 J21.2 J22.2 J22.3 J22.4 J22.5 J23.2 J23.3 J23.4 J23.5 J24.2 J24.3 J24.4 J24.5 J25.2 J25.3 J25.4 J25.5 J26.2 J26.3 J26.4 J26.5 J27.2 J27.3 J27.4 J27.5 J28.2 J28.3 J28.4 J28.5 J29.2 J29.3 J29.4 J29.5 J30.2 J30.3 J30.4 J30.5 J31.2 J31.3 J31.4 J31.5 JP1.2 JP2.1 JP4.2 JP6.2 JP7.2 JP8.2 JP10.2 Q1.2(EMITTER) Q2.2(EMITTER) R13.2 R14.2 R15.2 R25.2 R26.2 R27.2 R62.2 R63.2 R115.1 R124.1 R129.1 R134.1 R146.1 R147.1 R151.2 R152.2 R153.2 R154.2 R155.2 R156.2 R157.2 R158.2 R159.2 R160.2 R161.2 R162.2 SW1.2 SW1.3 TP1.1(TP) TP2.1(TP) TP3.1(TP) TP4.1(TP) TP5.1(TP) TP8.1(TP) TP9.1(TP) TP10.1(TP) TP11.1(TP) TP12.1(TP) TP13.1(TP) U1.57(EPAD) U2.57(EPAD) U3.1(GND0) U4.7(GND) U4.9(3A) U4.10(OE3) U4.12(4A) U4.13(OE4) U7.1(VeeT) U7.3(Tx_Disable) U7.9(VeeR) U7.10(VeeR) U7.11(VeeR) U7.14(VeeR) U7.17(VeeT) U7.20(VeeT) U8.1(VeeT) U8.3(Tx_Disable) U8.9(VeeR) U8.10(VeeR) U8.11(VeeR) U8.14(VeeR) U8.17(VeeT) U8.20(VeeT) U9.6(PGND) U9.16(LFB) U10.6(PGND) U10.16(LFB) U11.6(PGND) U11.16(LFB) U12.6(PGND) U12.16(LFB) Y1.2(GND) Y3.2(GND)
GNDE: C99.2 C101.2 C105.2 C109.2 C113.2 C117.2 C119.2 C121.2 C122.2 C123.2 CON1.9(Shield1) CON1.10(Shield2) J9.7(Shield1) J9.8(Shield2) J9.9(NC1) J9.10(NC2) R62.1 R63.1 U6.17(GND) U6.18(GND) U7.23(GND) U7.33(GND) U7.34(GND) U7.35(GND) U7.36(GND) U7.37(GND) U7.38(GND) U7.39(GND) U7.40(GND) U7.41(GND) U7.42(GND) U8.23(GND) U8.33(GND) U8.34(GND) U8.35(GND) U8.36(GND) U8.37(GND) U8.38(GND) U8.39(GND) U8.40(GND) U8.41(GND) U8.42(GND)
SGND_U9: C167.2 R113.1 R114.2 R115.2 U9.4(CG) U9.11(SHDN) U9.12(SDI) U9.13(SGND)
SGND_U10: C180.2 R118.2 R119.2 R120.2 R121.2 R122.2 R124.2 U10.4(CG) U10.11(SHDN) U10.12(SDI) U10.13(SGND)
SGND_U11: C189.2 R126.2 R128.2 R129.2 U11.4(CG) U11.11(SHDN) U11.12(SDI) U11.13(SGND)
SGND_U12: C201.2 R132.1 R133.2 R134.2 U12.4(CG) U12.11(SHDN) U12.12(SDI) U12.13(SGND)
VCC_3.3V: C140.1 C141.1 C143.1 C150.1 C151.1 C153.1 C199.1 C200.1 D1.1 D2.1 D3.1 D4.1 D5.1 D6.1 J9.1 J9.6 JP49.1 L1.1 L2.2 L3.1 L4.2 L20.2 R88.2 R89.2 R90.2 R91.2 R92.2 R100.2 R101.2 R102.2 R103.2 R104.2 R110.1 R125.1 R131.1 U12.3(SFB)
VCC_5V: F1.2 JP30.1 JP42.1 JP46.1 JP51.1 R111.2 TP15.1(TP)
VDD_1.0V: C187.1 C188.1 JP44.1 L16.2 R127.1 U11.3(SFB)
GEN_VDDO: C1.1 C2.1 C4.1 C5.1 C51.1 C52.1 C53.1 C178.1 C179.1 JP39.1 L12.2 R1.1 R2.1 R8.1 R22.1 R24.1 R117.1 R145.1 R148.2 U3.4(VCC) U4.1(OE1) U4.4(OE2) U4.14(VCC) U10.3(SFB) Y1.4(VCC0) Y3.4(VCC0)
MDC: J9.2 TP6.1(TP) U4.2(1A) U4.5(2A)
MDIO: J9.5 R22.2 R23.1 TP7.1(TP) U1.8(MDIO) U2.8(MDIO)
U1_1.8V: JP25.1 JP26.1 JP27.1 JP28.1
U1_AVDD_1.8V: C33.1 C34.1 C35.1 C36.1 C37.1 C38.1 C39.1 C40.1 C156.1 C157.1 C158.1 L5.1 R9.2 TP14.1(TP) U1.19(AVDD18) U1.26(AVDD18) U1.38(AVDD18)
U1_AVDD_3.3V: C41.1 C42.1 C43.1 C44.1 C45.1 C203.1 C204.1 C206.1 L21.1 TP27.1(TP) U1.20(AVDD33) U1.25(AVDD33)
U1_AVDDC_1.8V: C29.1 C30.1 C31.1 C32.1 C161.1 C162.1 L6.1 TP16.1(TP) U1.35(AVDDC18)
U1_AVDDF_1.8V: C25.1 C26.1 C27.1 C28.1 C163.1 C164.1 L8.1 TP17.1(TP) U1.3(AVDD18)
U1_CLK125: C14.1 J2.1 U1.9(CLK125)
U1_CONFIG: JP57.1 R149.1 U1.15(CONFIG)
U1_LED_0: JP11.5 R28.2 U1.14(LED[0])
U1_LED_1: JP11.3 JP56.1 R163.1 U1.13(LED[1])
U1_LED_2: INTn_1.1(TP) JP12.1 U1.12(LED[2]/INTn)
U1_MDC: U1.7(MDC) U4.3(1Y)
U1_MDI_N_0: R41.2 R42.1 U1.27(MDIN[0])
U1_MDI_N_1: R45.2 R47.1 U1.23(MDIN[1])
U1_MDI_N_2: R51.2 R53.1 U1.21(MDIN[2])
U1_MDI_N_3: R57.2 R59.1 U1.17(MDIN[3])
U1_MDI_P_0: R36.2 R40.1 U1.28(MDIP[0])
U1_MDI_P_1: R39.1 R43.2 U1.24(MDIP[1])
U1_MDI_P_2: R48.1 R49.2 U1.22(MDIP[2])
U1_MDI_P_3: R54.1 R55.2 U1.18(MDIP[3])
U1_RESETn: JP3.4 R1.2 U1.16(RESETn)
U1_RX_CLK: R136.1 R140.1 U1.46(RX_CLK)
U1_RX_CLK1: JP23.11 R140.2
U1_RX_CTRL: JP23.1 U1.43(RX_CTRL)
U1_RXD_0: JP23.3 U1.44(RXD[0])
U1_RXD_1: JP23.5 U1.45(RXD[1])
U1_RXD_2: JP23.7 U1.47(RXD[2])
U1_RXD_3: JP23.9 U1.48(RXD[3])
U1_SIN_N: C137.1 R86.2 R87.2 U1.2(S_INN)
U1_SIN_N_U2_SOUT_N: R87.1 R109.1
U1_SIN_P: C136.1 R84.2 R85.2 U1.1(S_INP)
U1_SIN_P_U2_SOUT_P: R84.1 R106.1
U1_SOUT_N: C144.2 R95.2 R96.2 U1.5(S_OUTN)
U1_SOUT_N_U2_SIN_N: R96.1 R105.1
U1_SOUT_P: C145.2 R93.2 R94.2 U1.4(S_OUTP)
U1_SOUT_P_U2_SIN_P: R93.1 R97.1
U1_TX_CLK: JP55.11 R138.1 R142.1 U1.53(TX_CLK)
U1_TX_CLK1: JP24.11 R142.2
U1_TX_CTRL: JP24.1 JP55.1 U1.56(TX_CTRL)
U1_TXD_0: JP24.3 JP55.3 U1.50(TXD[0])
U1_TXD_1: JP24.5 JP55.5 U1.51(TXD[1])
U1_TXD_2: JP24.7 JP55.7 U1.54(TXD[2])
U1_TXD_3: JP24.9 JP55.9 U1.55(TXD[3])
U1_V18: JP4.1 R8.2 U1.10(VDDO_SEL)
U1_VDD_1.0V: C8.1 C9.1 C10.1 C11.1 C12.1 C13.1 C15.1 C185.1 C186.1 L15.1 TP23.1(TP) U1.6(DVDD) U1.40(DVDD_OUT) U1.42(DVDD)
U1_VDD_3.3V: C22.1 C46.1 C47.1 C48.1 C49.1 C50.1 C194.1 C195.1 C196.1 L18.1 TP25.1(TP) U1.36(REG_IN)
U1_VDDO: C16.1 C17.1 C18.1 C19.1 C20.1 C21.1 C176.1 C177.1 L13.1 TP21.1(TP) U1.11(VDDO) U1.49(VDDO) U1.52(VDDO)
U1_XTAL1: R3.1 R4.2 R5.2 U1.34(XTAL1)
U1_XTAL2: R6.1 U1.33(XTAL2)
U2_1.8V: JP31.1 JP32.1 JP33.1 JP34.1
U2_AVDD_1.8V: C80.1 C81.1 C82.1 C83.1 C84.1 C85.1 C86.1 C87.1 C170.1 C171.1 L9.1 TP18.1(TP) U2.19(AVDD18) U2.26(AVDD18) U2.38(AVDD18) U2.39(AVDD18_OUT)
U2_AVDD_3.3V: C88.1 C89.1 C90.1 C91.1 C92.1 C207.1 C208.1 L22.1 TP28.1(TP) U2.20(AVDD33) U2.25(AVDD33)
U2_AVDDC_1.8V: C76.1 C77.1 C78.1 C79.1 C172.1 C173.1 L10.1 TP19.1(TP) U2.35(AVDDC18)
U2_AVDDF_1.8V: C72.1 C73.1 C74.1 C75.1 C174.1 C175.1 L11.1 TP20.1(TP) U2.3(AVDD18)
U2_CLK125: C63.1 J10.1 U2.9(CLK125)
U2_CONFIG: JP58.1 R150.1 U2.15(CONFIG)
U2_LED_0: JP13.5 R31.2 U2.14(LED[0])
U2_LED_1: JP13.3 JP54.1 R164.1 U2.13(LED[1])
U2_LED_2: INTn_2.1(TP) JP14.1 U2.12(LED[2]/INTn)
U2_MDC: U2.7(MDC) U4.6(2Y)
U2_MDI_N_0: R67.2 R68.1 U2.27(MDIN[0])
U2_MDI_N_1: R72.2 R73.1 U2.23(MDIN[1])
U2_MDI_N_2: R77.2 R78.1 U2.21(MDIN[2])
U2_MDI_N_3: R82.2 R83.1 U2.17(MDIN[3])
U2_MDI_P_0: R64.1 R65.2 U2.28(MDIP[0])
U2_MDI_P_1: R69.1 R70.2 U2.24(MDIP[1])
U2_MDI_P_2: R74.1 R75.2 U2.22(MDIP[2])
U2_MDI_P_3: R79.1 R80.2 U2.18(MDIP[3])
U2_RESETn: JP3.2 R2.2 U2.16(RESETn)
U2_RX_CLK: R139.1 R141.2 U2.46(RX_CLK)
U2_RX_CLK1: JP24.12 R141.1
U2_RX_CTRL: JP24.2 U2.43(RX_CTRL)
U2_RXD_0: JP24.4 U2.44(RXD[0])
U2_RXD_1: JP24.6 U2.45(RXD[1])
U2_RXD_2: JP24.8 U2.47(RXD[2])
U2_RXD_3: JP24.10 U2.48(RXD[3])
U2_SIN_N: C147.1 R99.2 R105.2 U2.2(S_INN)
U2_SIN_P: C146.1 R97.2 R98.2 U2.1(S_INP)
U2_SOUT_N: C154.2 R108.2 R109.2 U2.5(S_OUTN)
U2_SOUT_P: C155.2 R106.2 R107.2 U2.4(S_OUTP)
U2_TX_CLK: JP53.11 R137.1 R143.2 U2.53(TX_CLK)
U2_TX_CLK1: JP23.12 R143.1
U2_TX_CTRL: JP23.2 JP53.1 U2.56(TX_CTRL)
U2_TXD_0: JP23.4 JP53.3 U2.50(TXD[0])
U2_TXD_1: JP23.6 JP53.5 U2.51(TXD[1])
U2_TXD_2: JP23.8 JP53.7 U2.54(TXD[2])
U2_TXD_3: JP23.10 JP53.9 U2.55(TXD[3])
U2_V18: JP8.1 R24.2 U2.10(VDDO_SEL)
U2_VDD_1.0V: C58.1 C59.1 C60.1 C61.1 C62.1 C64.1 C191.1 C193.1 L17.1 TP24.1(TP) U2.6(DVDD) U2.40(DVDD_OUT) U2.42(DVDD)
U2_VDD_3.3V: C93.1 C94.1 C95.1 C96.1 C97.1 C197.1 C198.1 L19.1 TP26.1(TP) U2.36(REG_IN)
U2_VDDO: C65.1 C66.1 C67.1 C68.1 C69.1 C70.1 C182.1 C184.1 L14.1 TP22.1(TP) U2.11(VDDO) U2.49(VDDO) U2.52(VDDO)
U2_XTAL1: R17.1 R18.2 R19.2 U2.34(XTAL1)
U2_XTAL2: R21.1 U2.33(XTAL2)
N16787604: D3.2 R30.1
N16796830: JP1.1 Y1.1(EN)
N16796833: R4.1 Y1.3(OUT)
N16796834: C3.1 J1.1 R3.2
N16796839: C6.1 R5.1 Y2.2
N16994346: R10.2 R11.2 R14.1 U1.32(HSDACP)
N16994348: R12.2 R15.1 R16.1 U1.31(HSDACN)
N17016825: C54.1 J8.1 R17.2
N17016957: R18.1 Y3.3(OUT)
N17016970: C55.1 R19.1 Y4.2
N17016978: C56.1 R20.1 R21.2
N17193751: JP2.3 U3.2(~{RESET})
N17251537: JP13.2 JP13.4 JP13.6 JP13.8 JP58.2
N17251820: D6.2 R33.1
N17493866: JP5.2 R12.1
N17495532: JP5.1 R11.1
N17503153: JP7.1 Y3.1(EN)
N17787307: JP2.2 JP3.1 JP3.3
N17830081: JP11.2 JP11.4 JP11.6 JP11.8 JP57.2
N17893687: R65.1 U6.11(TRD1_P)
N17893693: R67.1 U6.10(TRD1_M)
N17893695: R70.1 U6.4(TRD2_P)
N17893699: R75.1 U6.3(TRD3_P)
N17893703: R77.1 U6.2(TRD3_M)
N17893707: R80.1 U6.8(TRD4_P)
N17893711: R82.1 U6.9(TRD4_M)
N18175709: R72.1 U6.5(TRD2_M)
N18237123: R13.1 U1.30(RSET)
N18290180: JP17.1 R48.2 R50.1
N18290184: JP17.2 R50.2 R53.2
N18290198: R57.1 U5.2(TD1_P)
N18290204: R55.1 U5.3(TD1_M)
N18290208: R51.1 U5.5(TD2_P)
N18290216: R49.1 U5.6(TD2_M)
N18290228: R45.1 U5.8(TD3_P)
N18290246: JP18.1 R54.2 R56.1
N18290250: JP18.2 R56.2 R59.2
N18290323: R43.1 U5.9(TD3_M)
N18290640: JP15.1 R37.1 R40.2
N18290658: JP15.2 R37.2 R42.2
N18290664: CON1.2(DA_M) U5.14(MX4_P)
N18290670: CON1.1(DA_P) U5.13(MX4_M)
N18290676: CON1.3(DB_P) U5.16(MX3_M)
N18290682: CON1.6(DB_M) U5.17(MX3_P)
N18290688: CON1.4(DC_P) U5.19(MX2_M)
N18290694: CON1.5(DC_M) U5.20(MX2_P)
N18290700: CON1.7(DD_P) U5.22(MX1_M)
N18290706: CON1.8(DD_M) U5.23(MX1_P)
N18290712: C105.1 R38.1
N18290718: C118.1 R52.2 U5.21(MCT2)
N18290720: C120.1 R58.2 U5.24(MCT1)
N18290726: C100.1 R38.2 U5.15(MCT4)
N18290728: C109.1 R46.1
N18290732: C113.1 R52.1
N18290736: C98.1 R46.2 U5.18(MCT3)
N18290738: C117.1 R58.1
N18290828: R36.1 U5.12(TD4_M)
N18290888: JP16.1 R39.2 R44.1
N18290892: JP16.2 R44.2 R47.2
N18290908: R41.1 U5.11(TD4_P)
N18307922: JP19.1 R64.2 R66.1
N18307926: JP19.2 R66.2 R68.2
N18317435: JP20.1 R69.2 R71.1
N18317437: JP20.2 R71.2 R73.2
N18317956: JP21.1 R74.2 R76.1
N18317958: JP21.2 R76.2 R78.2
N18318493: JP22.1 R79.2 R81.1
N18318495: JP22.2 R81.2 R83.2
N18570142: JP12.2 R30.2
N18601588: JP6.1 U1.29(TSTPT)
N18793953: C7.1 R6.2 Y2.1
N19074906: JP10.1 U2.29(TSTPT)
N19074920: R25.1 U2.30(RSET)
N19074934: JP9.1 R27.1 U2.31(HSDACN)
N19074982: JP9.2 R26.1 U2.32(HSDACP)
N19224300: JP47.1 JP48.1 JP49.2 JP50.1 JP52.1
N19224342: C190.2 C192.2 JP46.2 R130.1 U11.8(PVIN)
N19224390: C202.2 C205.2 JP51.2 R135.1 U12.8(PVIN)
N19224537: JP50.2 L21.2
N19224649: C201.1 R135.2 U12.1(ILIM) U12.9(SVIN)
N19224675: R126.1 U11.14(VSET)
N19224677: L16.1 U11.5(SW1) U11.7(SW2)
N19224683: C189.1 R130.2 U11.1(ILIM) U11.9(SVIN)
N19224747: R128.1 U11.15(PSET)
N19224753: JP43.2 L15.2
N19224758: JP43.1 JP44.2 JP45.1
N19224792: D11.1 R131.2
N19224808: R132.2 U12.14(VSET)
N19224948: L20.1 U12.5(SW1) U12.7(SW2)
N19224958: JP52.2 L22.2
N19224996: R133.1 U12.15(PSET)
N19225038: JP45.2 L17.2
N19225131: D10.1 R125.2
N19227820: JP39.2 JP40.1 JP41.1
N19228113: JP26.2 L6.2
N19228189: C181.2 C183.2 JP42.2 R123.1 U10.8(PVIN)
N19228203: R113.2 U9.14(VSET)
N19228243: C168.2 C169.2 JP30.2 R116.1 U9.8(PVIN)
N19228291: C167.1 R116.2 U9.1(ILIM) U9.9(SVIN)
N19228315: JP25.2 L5.2
N19228347: C165.1 C166.1 JP29.2 L7.2 R112.1 U9.3(SFB)
N19228371: JP35.2 JP36.2 JP37.2 JP38.2 U10.14(VSET)
N19228441: D8.1 R110.2
N19228445: D9.1 R117.2
N19228465: L7.1 U9.5(SW1) U9.7(SW2)
N19228523: R114.1 U9.15(PSET)
N19228594: JP28.2 L8.2
N19228794: JP41.2 L14.2
N19228818: JP40.2 L13.2
N19228834: L12.1 U10.5(SW1) U10.7(SW2)
N19228838: C180.1 R123.2 U10.1(ILIM) U10.9(SVIN)
N19228887: R118.1 U10.15(PSET)
N19228961: JP27.2 JP29.1 JP31.2
N19229117: JP33.2 L10.2
N19229193: JP32.2 L9.2
N19229239: JP34.2 L11.2
N19229269: JP36.1 R120.1
N19229277: C159.1 C160.1 F1.1 J20.1 J20.2
N19229287: D7.1 R111.1
N19241861: C142.1 L2.1 U7.15(VccR)
N19242097: C145.1 J14.1
N19242099: C144.1 J13.1
N19242143: C138.1 C139.1 L1.2 U7.16(VccT)
N19242271: C136.2 J11.1
N19242275: C137.2 J12.1
N19242333: R94.1 U7.18(TD+)
N19242335: R95.1 U7.19(TD-)
N19242343: R85.1 U7.13(RD+)
N19242345: R86.1 U7.12(RD-)
N19242395: R89.1 U7.6(MOD-DEF_0)
N19242397: R90.1 U7.5(MOD-DEF_1)
N19242401: R91.1 U7.4(MOD-DEF_2)
N19242403: R92.1 U7.2(TxFault)
N19242417: R88.1 U7.8(LOS)
N19251259: C152.1 L4.1 U8.15(VccR)
N19251492: C155.1 J18.1
N19251494: C154.1 J17.1
N19251531: C148.1 C149.1 L3.2 U8.16(VccT)
N19251660: C146.2 J15.1
N19251670: C147.2 J16.1
N19251724: R107.1 U8.18(TD+)
N19251726: R108.1 U8.19(TD-)
N19251738: R98.1 U8.13(RD+)
N19251740: R99.1 U8.12(RD-)
N19251790: R101.1 U8.6(MOD-DEF_0)
N19251792: R102.1 U8.5(MOD-DEF_1)
N19251796: R103.1 U8.4(MOD-DEF_2)
N19251798: R104.1 U8.2(TxFault)
N19251812: R100.1 U8.8(LOS)
N19271739: C24.1 U1.41(REGCAP2)
N19272342: C24.2 U1.37(REGCAP1)
N19279105: C71.1 U2.41(REGCAP2)
N19280044: C71.2 U2.37(REGCAP1)
N19304511: C102.1 C103.1 C104.1 U5.10(TCT4)
N19306537: C106.1 C107.1 C108.1 U5.7(TCT3)
N19306786: C110.1 C111.1 C112.1 U5.4(TCT2)
N19307065: C114.1 C115.1 C116.1 U5.1(TCT1)
N19311353: C124.1 C125.1 C126.1 U6.12(TRCT1)
N19311558: C127.1 C128.1 C129.1 U6.6(TRCT2)
N19311775: C130.1 C131.1 C132.1 U6.1(TRCT3)
N19312774: C133.1 C134.1 C135.1 U6.7(TRCT4)
N19315408: C100.2 R35.1
N19315410: C101.1 R35.2
N19317022: C118.2 R60.1
N19317024: C119.1 R60.2
N19317288: C120.2 R61.1
N19317290: C121.1 R61.2
N19317557: C98.2 R34.1
N19317559: C99.1 R34.2
N19395566: C57.1 R23.2
N19411569: R20.2 Y4.1
N19626709: C23.1 R9.1 TP29.1(TP) U1.39(AVDD18_OUT)
N19642082: J6.1 R10.1
N19649053: J7.1 R16.2
N19712055: C194.2 J22.1
N19732438: C22.2 J4.1
N19876023: JP35.1 R119.1
N19879807: JP37.1 R121.1
N19880091: JP38.1 R122.1
N20143388: SW1.1 SW1.4 U3.3(~{MR})
N20247366: J26.1 R139.2
N20247420: J25.1 R137.2
N20250415: J24.1 R136.2
N20252579: J27.1 R138.2
N20326527: C23.2 J5.1
N20344726: C15.2 J3.1
N20356781: C156.2 J19.1
N20368817: C203.2 J23.1
N20438631: JP11.7 R146.2
N20438658: JP11.1 R145.2
N20438885: JP13.7 R147.2
N20438965: JP13.1 R148.1
N20443704: JP53.2 R156.1
N20443713: JP53.4 R155.1
N20443722: JP53.6 R154.1
N20444307: JP53.8 R153.1
N20444316: JP53.10 R152.1
N20444325: JP53.12 R151.1
N20444660: JP55.2 R162.1
N20444664: JP55.4 R161.1
N20444668: JP55.6 R159.1
N20444672: JP55.8 R160.1
N20444676: JP55.10 R158.1
N20444680: JP55.12 R157.1
N20445311: J28.1 R149.2
N20445323: J29.1 R150.2
N20445616: JP14.2 R33.2
N20445860: J31.1 R164.2
N20445926: JP54.2 R32.2
N20446666: JP56.2 R29.2
N20446778: J30.1 R163.2
N20530843: Q2.1(BASE) R127.2
N20530844: D10.2 Q2.3(COLLECTOR)
N20531161: D8.2 Q1.3(COLLECTOR)
N20531162: Q1.1(BASE) R112.2
N20532282: D1.2 R28.1
N20532283: D4.2 R31.1
N20532284: D5.2 R32.1
N20532285: D2.2 R29.1
N20541225: JP47.2 L18.2
N20541237: JP48.2 L19.2

Not connected (* = marked no-connect by the designer): CON1 11(NC1) 12(NC2); SKT1 1(MT1) 2(MT2) 3(MT3) 4(MT4) 5(AL1) 6(AL2) 7(AL3) 8(AL4); SKT2 1(MT1) 2(MT2) 3(MT3) 4(MT4) 5(AL1) 6(AL2) 7(AL3) 8(AL4); U4 8(3Y)* 11(4Y)*; U6 13(K1)* 14(A1)* 15(K2)* 16(A2)* 19(NC1)* 20(NC2)*; U7 7(Rate_Select) 21(NC1) 22(NC2) 24(NC3) 25(NC4) 26(NC5) 27(NC6) 28(NC7) 29(NC8) 30(NC9) 31(NC10) 32(NC11); U8 7(Rate_Select)* 21(NC1)* 22(NC2)* 24(NC3)* 25(NC4)* 26(NC5)* 27(NC6)* 28(NC7)* 29(NC8)* 30(NC9)* 31(NC10)* 32(NC11)*; U9 2(LDR)* 10(PG)*; U10 2(LDR)* 10(PG)*; U11 2(LDR)* 10(PG)*; U12 2(LDR)* 10(PG)*

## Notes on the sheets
sheet 1
- 88E1512 / 88E1512P 56-QFN Evaluation
  Board (Schematics)
- Table of Contents
- Revision History
- Page No
- Description
- DATE
- REVISION
- DESCRIPTION
- 1
- Cover page
- 01/11/2016
- -
- Initial release
- 2
- Block Diagram
- 3
- 88E1512 / 88E1512P device U1
- 4
- 88E1512 / 88E1512P device U2
- 5
- LEDs - Configuration
- 6-7
- Copper Interfaces
- 8
- RGMII Loopback
- 9-10
- SGMII Interfaces
- 10
- Supplies 1
- 10
- Supplies 2
- Document Classification -Public
sheet 2
- TOP LEVEL BLOCK DIAGRAM
- H/w Reset
- O  S
  S  M
  C  A
- O  S
  S  M
  C  A
- MDC/MDIO
- OPTIONAL
- OPTIONAL
- XTAL
- RGMII INTERFACE
- XTAL
- POWER
- 88E1512 / 88E1512P
  RGMII/SGMII
  56QFN U1
- 88E1512 / 88E1512P
  RGMII/SGMII
  56QFN U2
- POWER
- SMA
- SMA
- LEDS
- LEDS
- SGMII INTERFACE
- CONFIG
- CONFIG
- OPTIONAL
- OPTIONAL
- HSDAC/TSTPTs
- HSDAC/TSTPTs
- Magnetic +
  Integrated RJ 45
- Magnetic
- SFP
- SFP
- RJ 45
- Document Classification -Public
sheet 3
- 88E1512/88E1512P DEVICE U1
- RefClkIn
- Def: 2-3
- Def: 3-4
- Def: 1-2
- Layout: Label all these as "GND"
- U1_VDD10
- Def: OFF
- Layout: Put the VIA for J3,J4, J5 to Power plane(s) close to the chip
- U1_VDD33
- U1_AVDDL
- HSDAC+
- HSDAC
- +
- Def: OFF
- -
- TstPt.
- Def: OFF
- HSDAC-
- Document Classification -Public
- NOTE: In an actual applicatoin, the capacitor between REGCAP1
  and REGCAP2 should not be populated if external regulators are
  used.
sheet 4
- 88E1512/88E1512P DEVICE U2
- RefClkIn
- MDC
- MDC
- MDIO
- MDIO
- GND
- Layout: Label all these as "GND"
- Def: OFF
- +
- HSDAC
- Def: OFF
- -
- Def: OFF
- Document Classification -Public
- NOTE: In an actual applicatoin, the capacitor between REGCAP1
  and REGCAP2 should not be populated if external regulators are
  used.
sheet 5
- LEDs-CONFIGURATION
- LED 0
- LED 1
- GREEN
- GREEN
- LED 2
- Remove JP56 and JP57 after PHY is configured when using PTP function.
- GREEN
- Def: ON
- Def: ON
- U1_TRIG_GEN
- Def: 3-4
- Def: ON
- LED 0
- LED 1
- GREEN
- GREEN
- U1_PTP_CLK
- Def: ON
- LED 2
- NOTE: The PTP clock should not be
  driven until the device is stabled
  and the hardware configuraiton has
  completed.
- GREEN
- U2_TRIG_GEN
- Def: 5-6
- Def: ON
- Def: ON
- Remove JP54 and JP58 after PHY is configured when using PTP function.
- Document Classification -Public
- U2_PTP_CLK
sheet 6
- U1 COPPER MEDIA
- Document Classification -Public
sheet 7
- U2 COPPER MEDIA
- Document Classification -Public
sheet 8
- RGMII LOOPBACK
- Def: OFF
- Def: 1-2
  Def: 3-4
  Def: 5-6
  Def: 7-8
  Def: 9-10
  Def: 11-12
- U1_RX_CLK
- U2_TX_CLK
- Def: OFF
- Def: 1-2
  Def: 3-4
  Def: 5-6
  Def: 7-8
  Def: 9-10
  Def: 11-12
- U1_TX_CLK
- U2_RX_CLK
- Layout: SMA J25 and Header JP 53 should have same trace length from the chip.
- Layout: SMA J27 and Header JP 54 should have same trace length from the chip.
- Document Classification -Public
sheet 9
- U1 SGMII Interface
- U1_S_IN_P
- U1_S_IN_N
- U1_S_OUT_N
- U1_S_OUT_P
- Document Classification -Public
sheet 10
- U2 SGMII Interface
- U2_S_IN_P
- U2_S_IN_N
- U2_S_OUT_N
- U2_S_OUT_P
- Document Classification -Public
sheet 11
- SUPPLIES PART 1
- Def: ON
- AVDD18_Noise_in
- Def: ON
- Def: ON
- Def: ON
- Def: ON
- Def: ON
- Def: ON
- Def: ON
- Def: ON
- Def: ON
- Def: ON-2.5V
- 1.5V       1.8V       2.5V       3.3V
- Def: ON
- Def: ON
- OFF
- OFF
- ON
- OFF
- Document Classification -Public
- Def: ON
- Warning: ONLY 1 jumper should be installed
- Def: ON
sheet 12
- SUPPLIES PART 2
- Def: ON
- Def: ON
- Def: ON
- Def: ON
- VDD33_Noise_in
- Def: OFF
- Def: OFF
- Def: ON
- AVDD33_Noise_in
- Def: ON
- Def: ON
- Document Classification -Public
- Def: ON
